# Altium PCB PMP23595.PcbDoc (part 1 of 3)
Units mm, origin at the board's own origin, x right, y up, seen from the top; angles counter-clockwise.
Board outline 121.92 x 78.74 mm, 6 copper layers (Layer 1, GND 1, Layer 3, Layer 4, GND 2, Layer 6), stack 2.208 mm thick; 236 components, 76 nets, 570 pads, 735 vias.
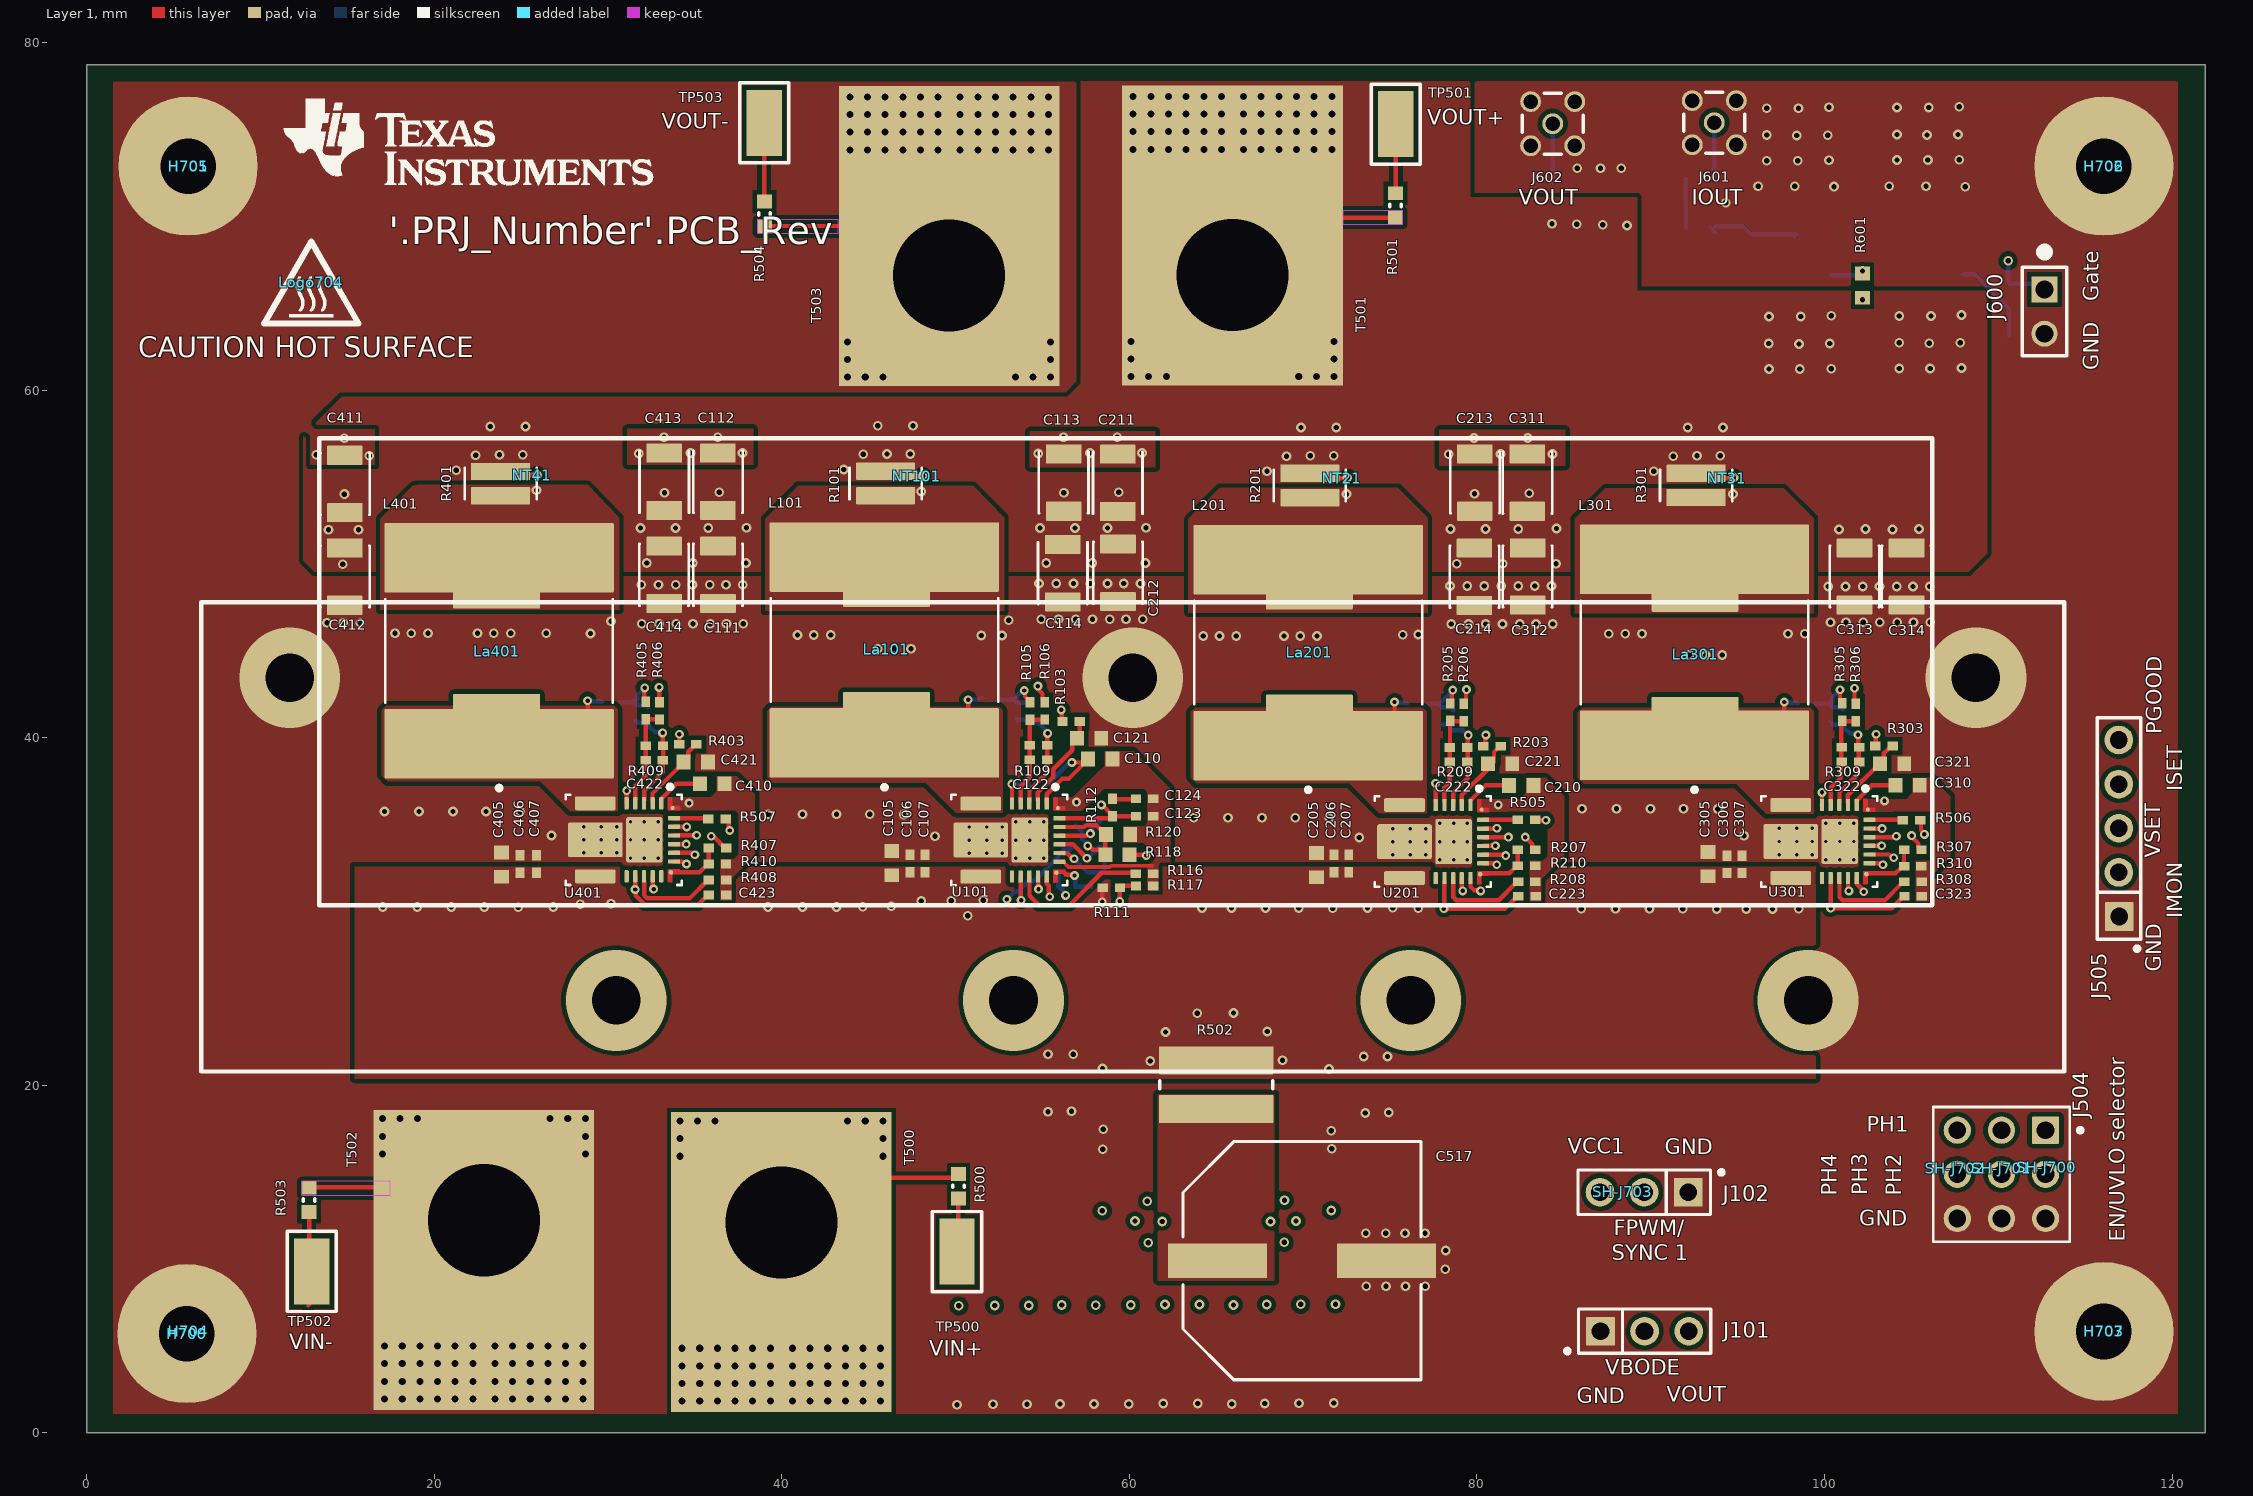
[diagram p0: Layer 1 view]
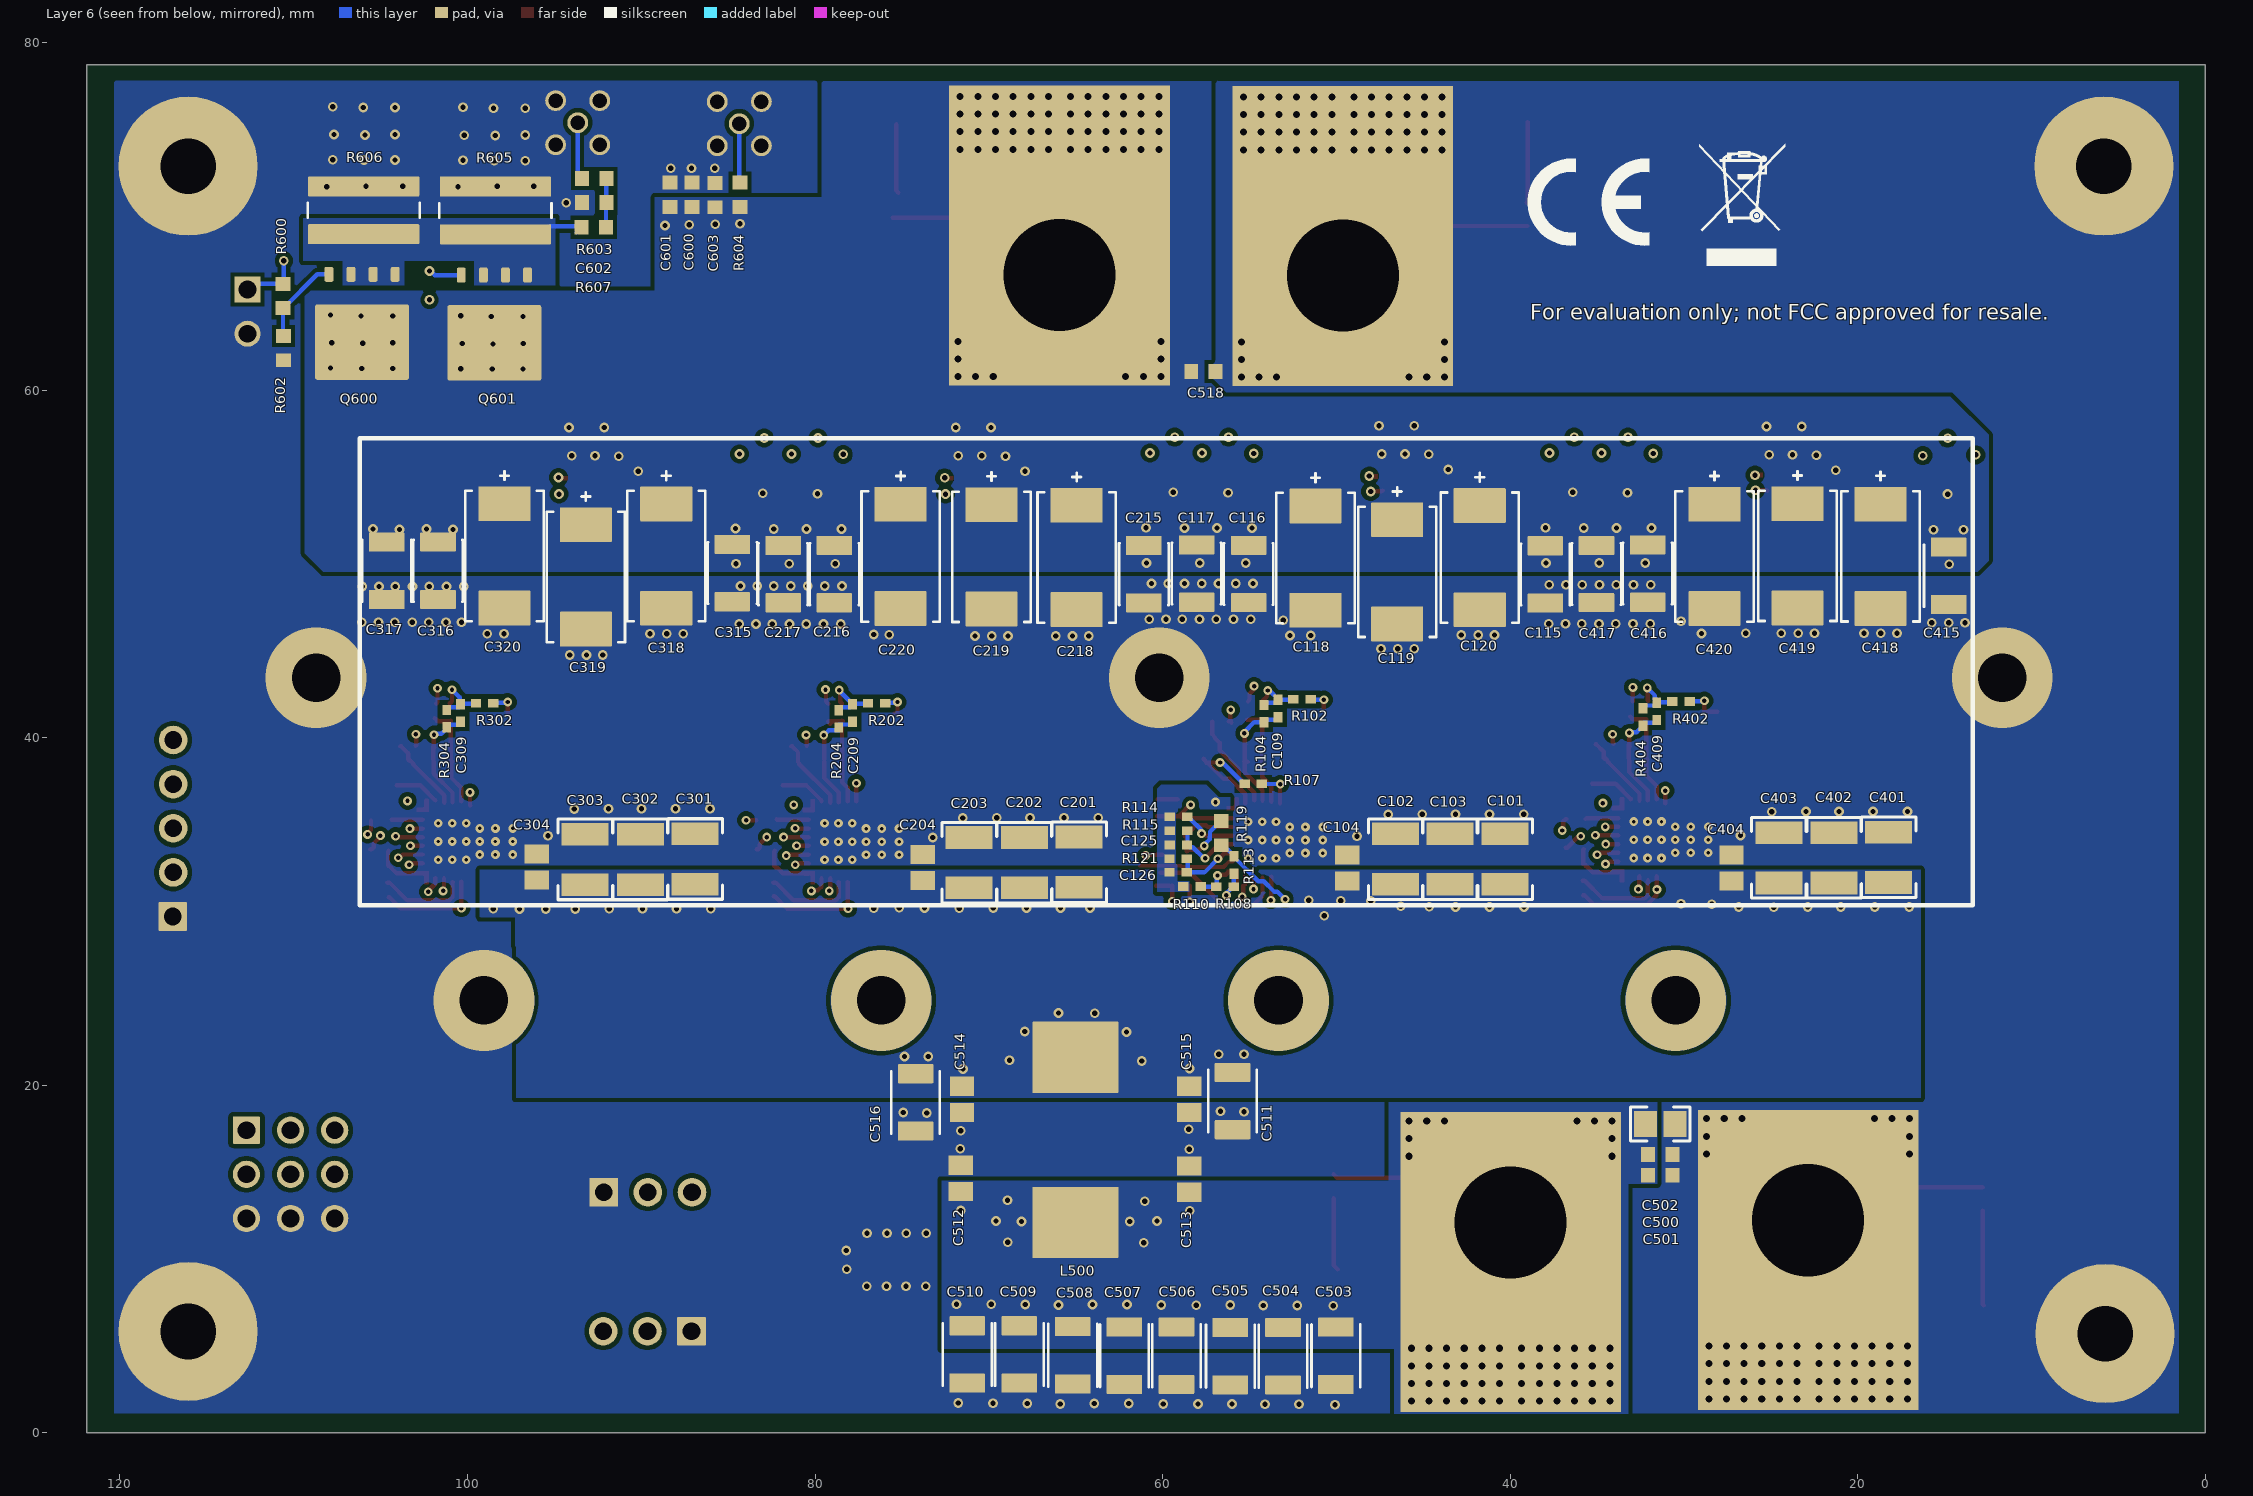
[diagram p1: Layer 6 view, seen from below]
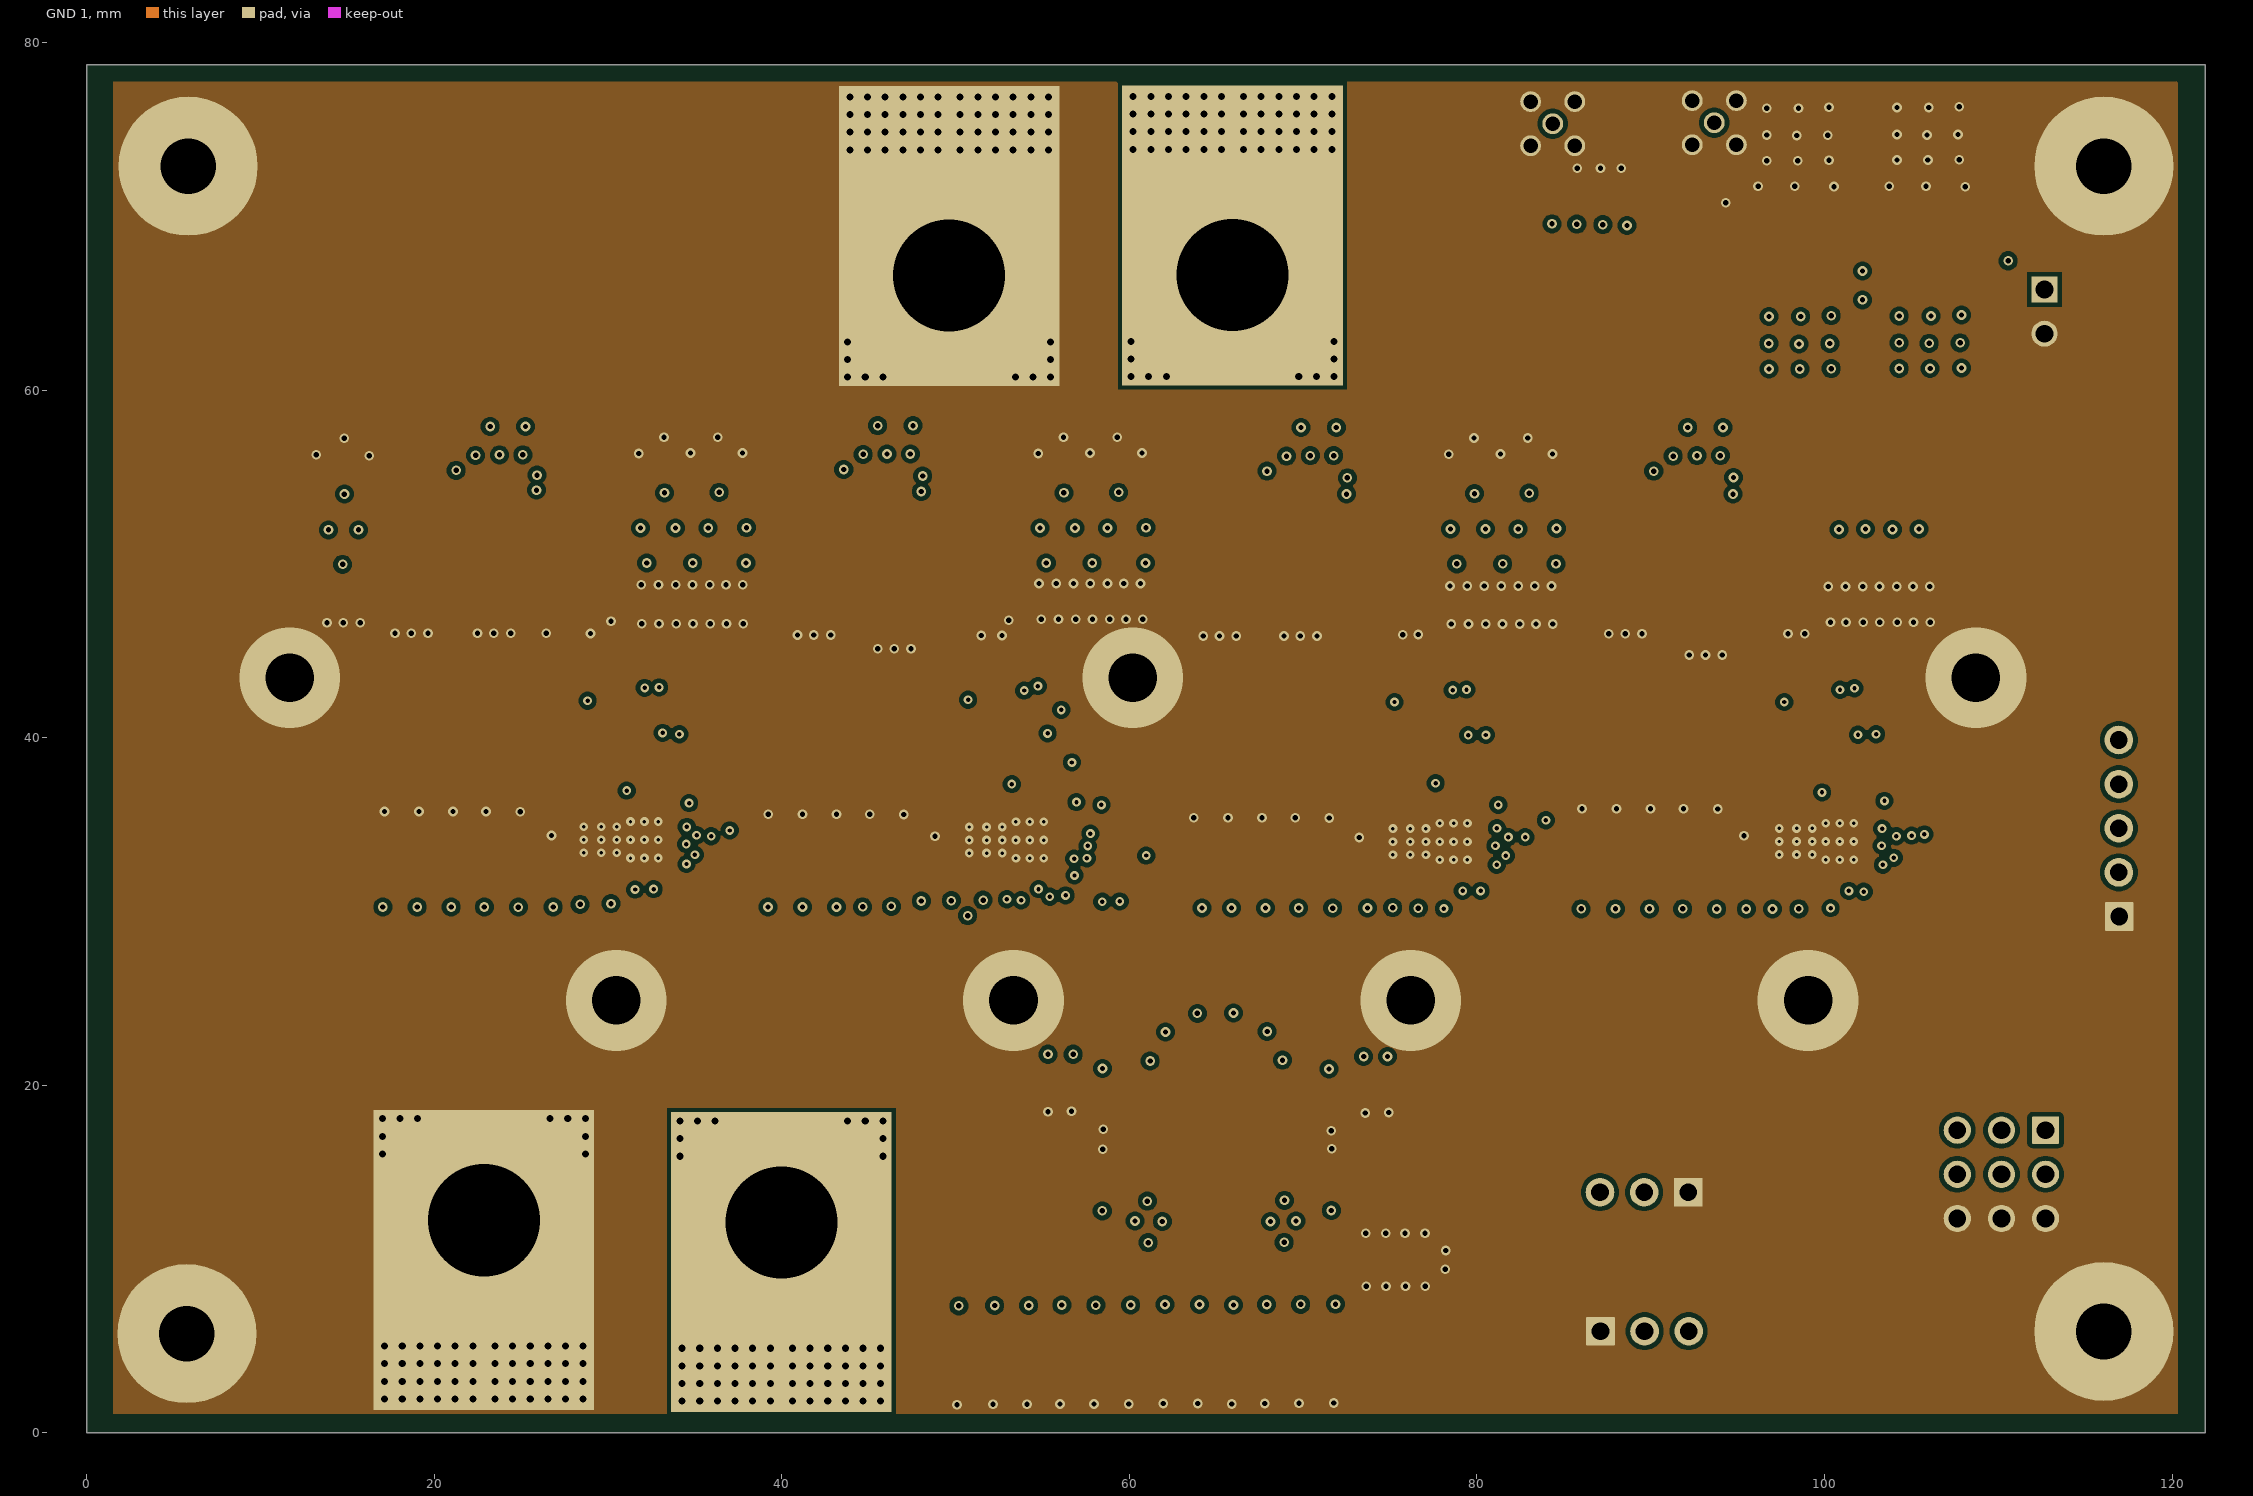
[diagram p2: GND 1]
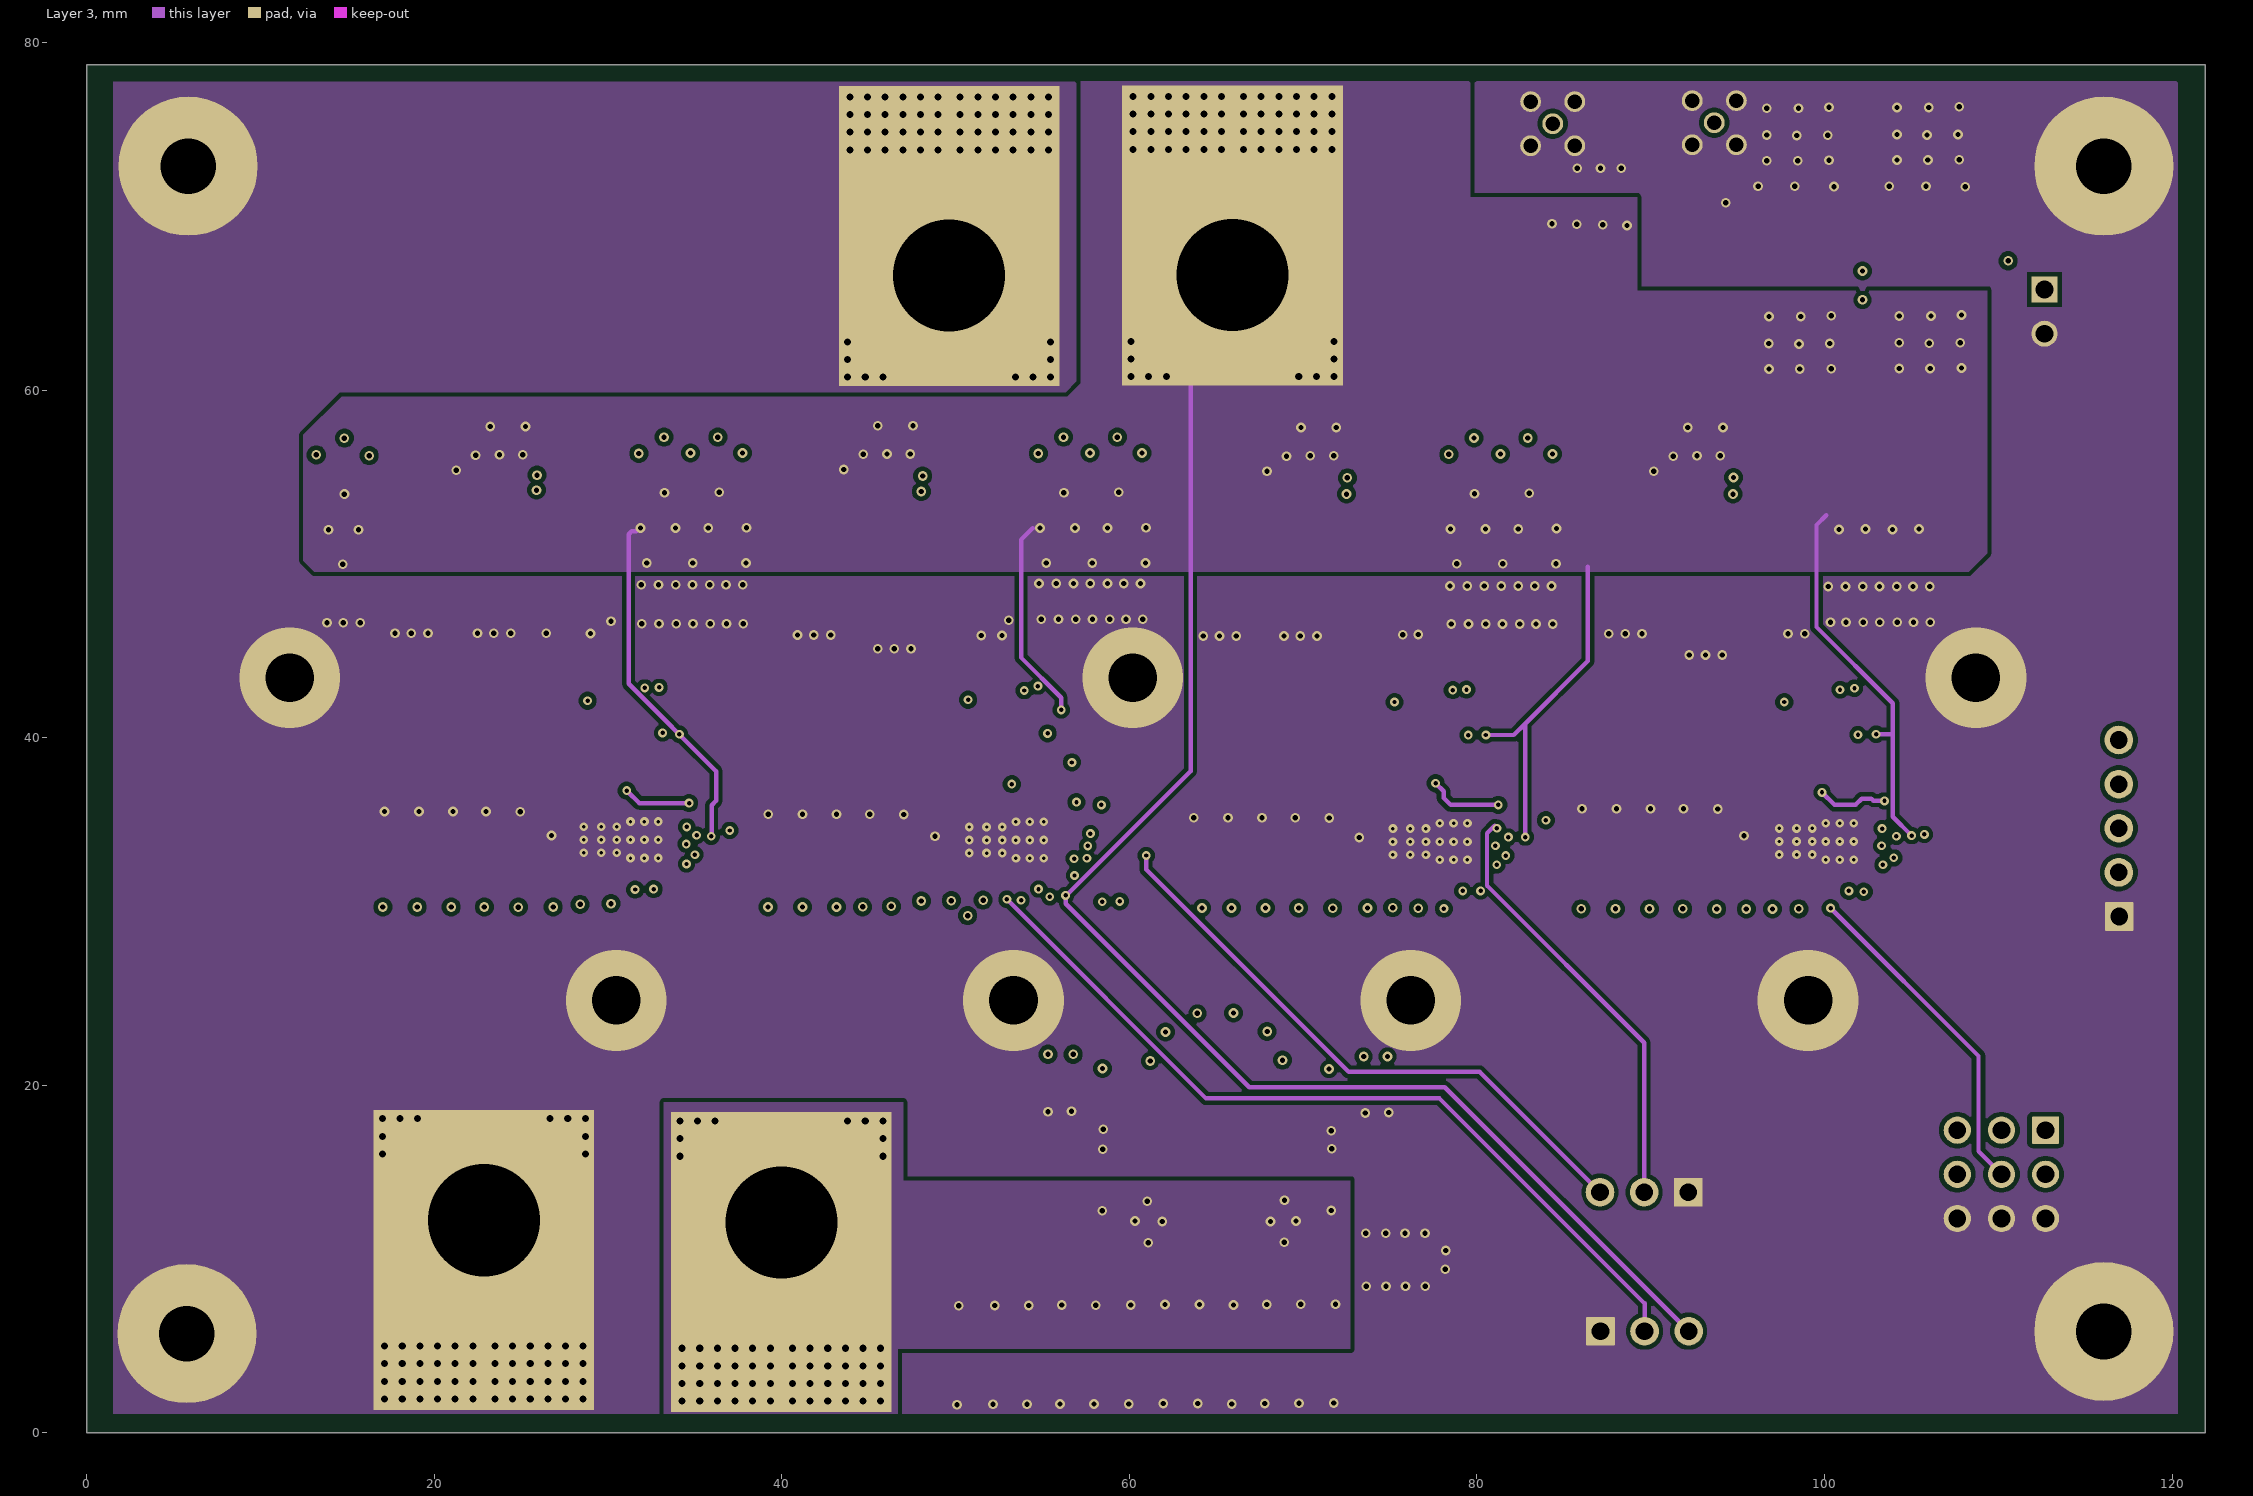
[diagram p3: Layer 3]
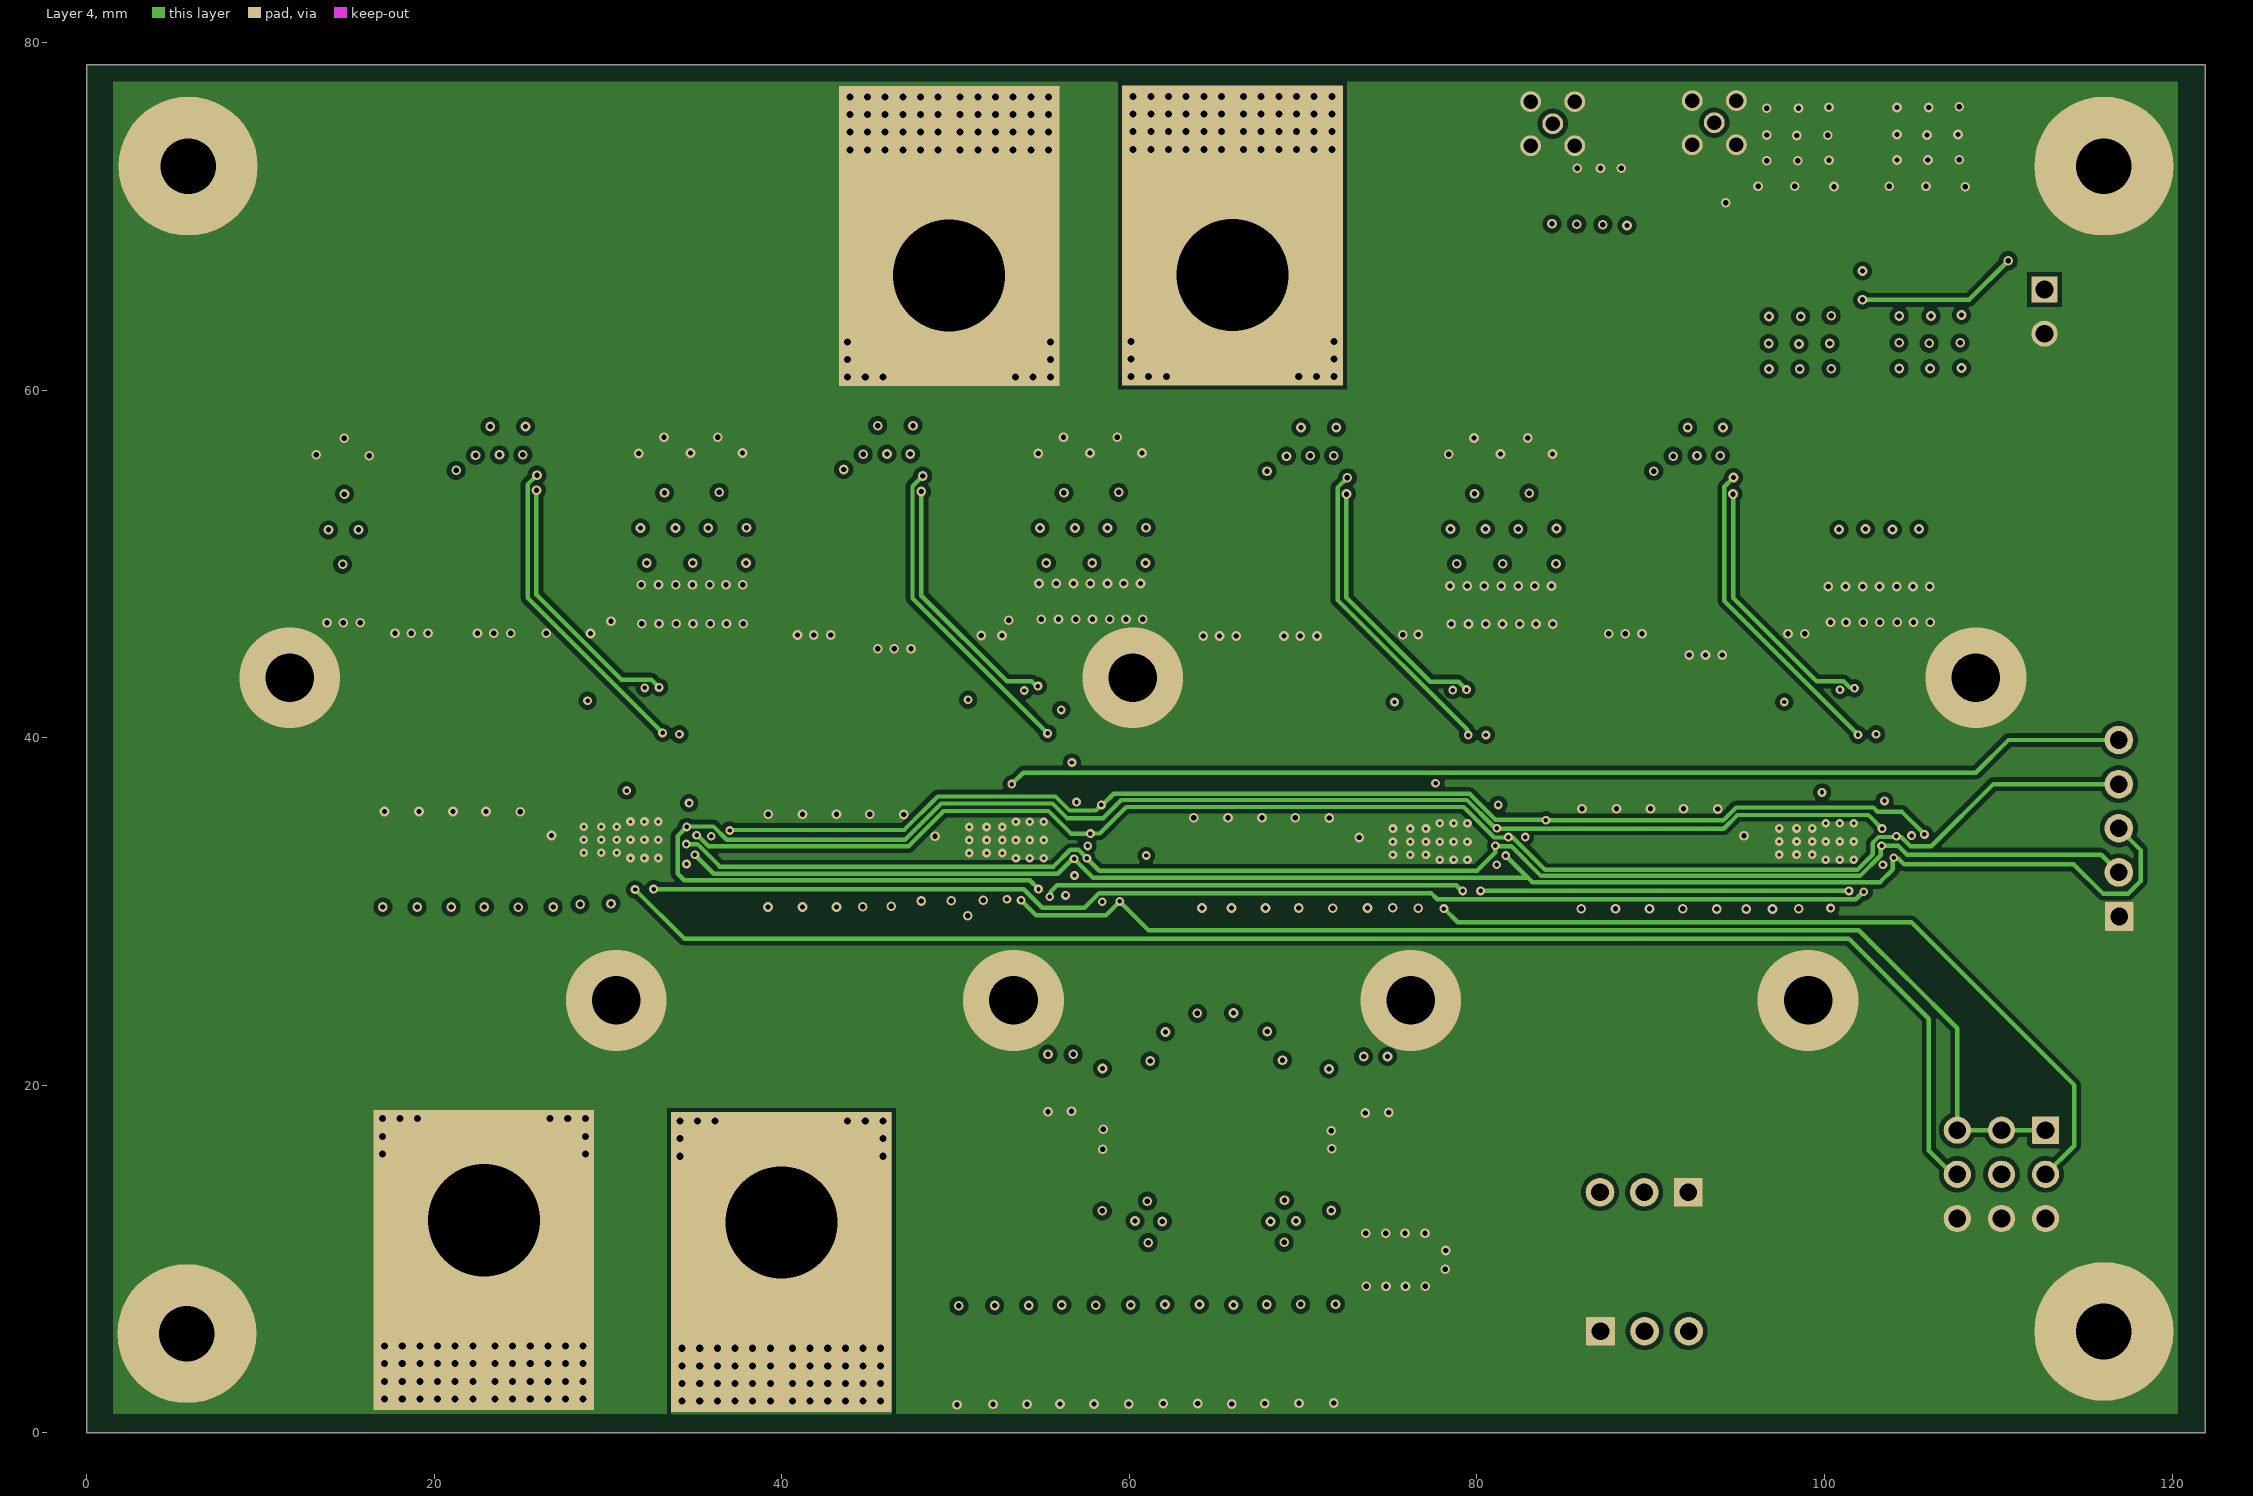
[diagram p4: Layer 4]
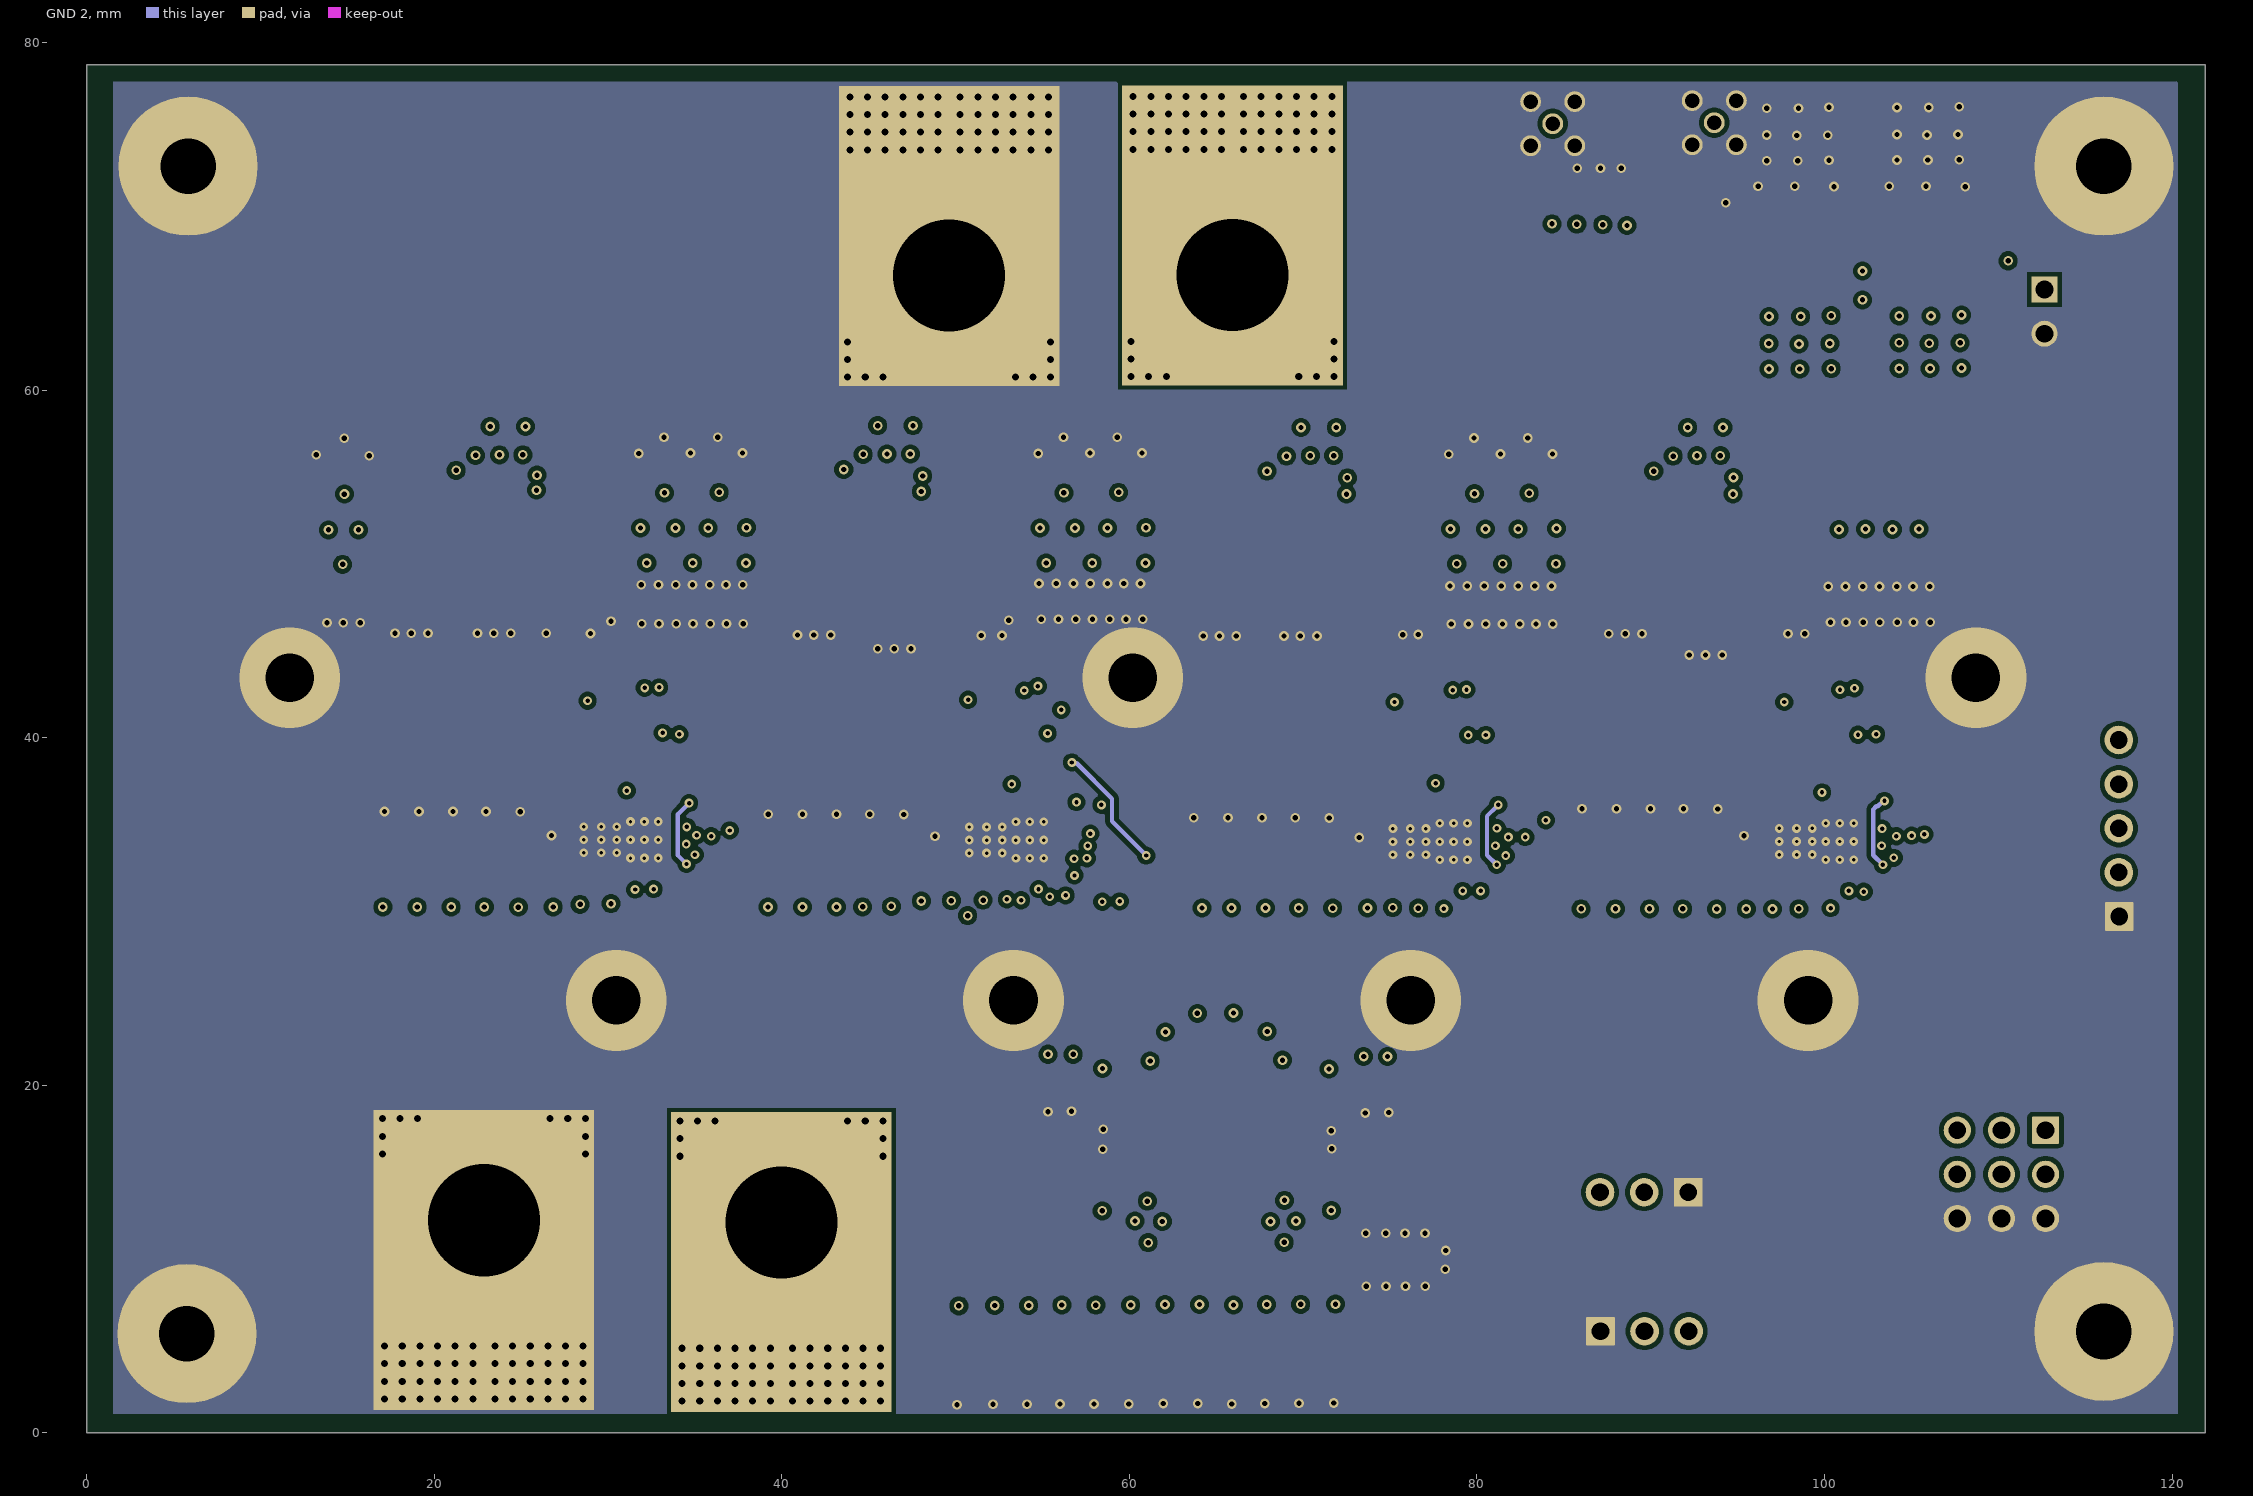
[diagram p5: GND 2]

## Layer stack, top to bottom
Top Solder: solder mask 0.0102, Solder Resist, Dk 3.5
Layer 1: signal copper 0.07
Dielectric 1: prepreg 0.0711, PP-006, Dk 4.1
GND 1: signal copper 0.07
Dielectric 3: prepreg 0.0711, PP-006, Dk 4.1
Layer 3: signal copper 0.07
Dielectric1: core 1.5037, FR-4 High Tg, Dk 4.8
Layer 4: signal copper 0.07
Dielectric 4: prepreg 0.0711, PP-006, Dk 4.1
GND 2: signal copper 0.07
Dielectric 2: prepreg 0.0711, PP-006, Dk 4.1
Layer 6: signal copper 0.07
Bottom Solder: solder mask 0.0102, Solder Resist, Dk 3.5

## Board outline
0,0 0,78.74 121.92,78.74 121.92,0

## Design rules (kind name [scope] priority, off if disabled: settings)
AcuteAngle [All] p1: minimum=4.50000000000000E+0001 checktracksonly=FALSE
AssemblyTestPointUsage [All] p1: valid=2
BoardOutlineClearance BoardOutlineClearance_MountingHoles [OnCopper and InComponentClass('Mounting Holes')] p1: gap=1 ignorepadtopadclearanceinfootprint=FALSE
BoardOutlineClearance BoardOutlineClearance_Poly [OnCopper and IsPoly] p2: gap=0.635 ignorepadtopadclearanceinfootprint=FALSE
BoardOutlineClearance [OnCopper and Not InComponentClass('Logo') and not InComponentClass('FiducialMark') and not InRegion(1000,500,4000,800) and not InPoly] p3: gap=1.016 ignorepadtopadclearanceinfootprint=FALSE
Clearance Clearance_Keepouts [((IsTrack Or IsArc) And Not InPoly) And IsFree and IsKeepOut vs ((IsTrack Or IsArc) And Not InPoly) And IsFree and IsKeepOut] p1: gap=0 ignorepadtopadclearanceinfootprint=FALSE
Clearance Clearance_Poly [InPolygon] p2: gap=0.254 ignorepadtopadclearanceinfootprint=TRUE
Clearance Clearance_FiducialMark [IsKeepOut and InComponentClass('FiducialMark') vs IsPad and InComponentClass('FiducialMark')] p3: gap=0 ignorepadtopadclearanceinfootprint=FALSE
Clearance [All] p4: gap=0.1 ignorepadtopadclearanceinfootprint=TRUE except(0.15: SMDPad-SMDPad; 0.2: Arc-Hole Track-Hole SMDPad-Hole THPad-Hole)
ComponentClearance ComponentClearance_MountingHoles_FiducialMarks [InComponentClass('Mounting Holes') vs InComponentClass('FiducialMark')] p1: gap=1.27 collisioncheckmode=3 verticalgap=0.254 showdistances=FALSE
ComponentClearance ComponentClearance_Shunt [InComponentClass('Header') vs InComponentClass('Shunt')] p2: gap=0 collisioncheckmode=3 verticalgap=0 showdistances=FALSE
ComponentClearance ComponentClearance_Logo [InComponentClass('Logo')] p3: gap=0.762 collisioncheckmode=3 verticalgap=0.254 showdistances=FALSE
ComponentClearance ComponentClearance_ScrewToNut [(HasFootprint('NY PMS 440 0025 PH')) vs (HasFootprint('Keystone_1902C'))] p4: gap=0.127 collisioncheckmode=3 verticalgap=0.254 showdistances=FALSE
ComponentClearance ComponentClearance_MountingHoles [InComponentClass('Mounting Holes')] p5: gap=2.54 collisioncheckmode=3 verticalgap=2540 showdistances=FALSE
ComponentClearance ComponentClearance_SmallPassives [HasFootprint('0201*') or HasFootprint('0402*') or HasFootprint('0508') or HasFootprint('0603*') or HasFootprint('0612') or HasFootprint('0805*') or HasFootprint('0815*') or HasFootprint('0830*') or HasFootprint('1206*') or HasFootprint('1210*') or HasFootprint('1808*') or HasFootprint('1812*') or HasFootprint('1825*') or HasFootprint('2010*') or HasFootprint('2220*') or HasFootprint('2225*') or HasFootprint('2512*') or HasFootprint('2728*') or HasFootprint('3518*') vs HasFootprint('0201*') or HasFootprint('0402*') or HasFootprint('0508') or HasFootprint('0603*') or HasFootprint('0612') or HasFootprint('0805*') or HasFootprint('0815*') or HasFootprint('0830*') or HasFootprint('1206*') or HasFootprint('1210*') or HasFootprint('1808*') or HasFootprint('1812*') or HasFootprint('1825*') or HasFootprint('2010*') or HasFootprint('2220*') or HasFootprint('2225*') or HasFootprint('2512*') or HasFootprint('2728*') or HasFootprint('3518*')] p6: gap=0.38 collisioncheckmode=3 verticalgap=0.254 showdistances=FALSE
ComponentClearance ComponentClearance_THtoSMT [IsThruComponent vs IsSMTComponent] p7: gap=0.762 collisioncheckmode=3 verticalgap=0.762 showdistances=FALSE
ComponentClearance ComponentClearance_THtoTH [IsThruComponent vs IsThruComponent] p8: gap=0.508 collisioncheckmode=3 verticalgap=0.762 showdistances=FALSE
ComponentClearance [All] p9: gap=0.508 collisioncheckmode=3 verticalgap=0.254 showdistances=FALSE
DiffPairsRouting [All] p1: maxlimit=2.54 minlimit=0.254 mostfreqgap=0.254 toplayer_minwidth=0.381 toplayer_maxwidth=0.381 toplayer_prefwidth=0.381 midlayer1_minwidth=0.381 midlayer1_maxwidth=0.381 midlayer1_prefwidth=0.381 midlayer2_minwidth=0.381 midlayer2_maxwidth=0.381 midlayer2_prefwidth=0.381 midlayer3_minwidth=0.381 midlayer3_maxwidth=0.381 midlayer3_prefwidth=0.381 midlayer4_minwidth=0.381 midlayer4_maxwidth=0.381 midlayer4_prefwidth=0.381 bottomlayer_minwidth=0.381 bottomlayer_maxwidth=0.381 bottomlayer_prefwidth=0.381 maxuncoupledlength=25.4
FabricationTestPointUsage TestPointUsage [All] p1: valid=2 allowmultiple=FALSE
FabricationTestpoint Testpoint [All] p1: side=3 testpointundercomponent=TRUE minsize=1.016 maxsize=2.54 preferedsize=1.524 minholesize=0 maxholesize=1.016 preferedholesize=0.813 testpointgrid=0.025 allowsidetop=TRUE allowsidebottom=TRUE usegrid=TRUE gridtolerance=0
FanoutControl Fanout_LCC [IsLCC] p1: bgadir=Out bgaviamode=Centered fanoutstyle=Auto fanoutdirection=Alternating viagrid=0.025 // Fanout_LCC (Default Rule)
FanoutControl Fanout_BGA [IsBGA] p2: bgadir=Out bgaviamode=Centered fanoutstyle=Auto fanoutdirection=Alternating viagrid=0.025 // Fanout_BGA (Default Rule)
FanoutControl Fanout_Default [All] p4: bgadir=Out bgaviamode=Centered fanoutstyle=Auto fanoutdirection=Alternating viagrid=0.025 // Fanout_Default (Default Rule)
FanoutControl Fanout_Small [(CompPinCount < 5)] p5: bgadir=Out bgaviamode=Centered fanoutstyle=Auto fanoutdirection=OutThenIn viagrid=0.025 // Fanout_Small (Default Rule)
HoleSize [All] p1: absolutevalues=TRUE maxlimit=7.62 minlimit=0.15 maxpercent=80.000 minpercent=20.000
HoleToHoleClearance [All] p1: gap=0.45 allowstackedmicrovias=TRUE
MinimumAnnularRing MinimumAnnularRing_ThermalPadVias [IsVia and InAnyComponent] p1: minimumring=0.075
MinimumAnnularRing [All] p2: minimumring=0.075
MinimumSolderMaskSliver MinimumSolderMaskSliver_Logo [InComponentClass('Logo') vs InComponentClass('Logo')] p1: minsoldermaskwidth=0.018
MinimumSolderMaskSliver [All] p2: minsoldermaskwidth=0.1
PlaneConnect [All] p1: planeconnectstyle=Relief reliefexpansion=0.254 reliefentries=4 reliefconductorwidth=0.254 reliefairgap=0.254
PolygonConnect [All] p1: connectstyle=Direct reliefconductorwidth=0.254 reliefentries=4 polygonreliefangle="90 Angle" airgapwidth=0.254
RoomDefinition 2 [InComponentClass('2')] p1: confinementstyle=ConfineIn formatcopy=TRUE lockcomponents=FALSE outline 57.301,51.868 57.301,57.484 77.85,57.496 81.916,57.496 83.847,52.13 84.314,38.343 84.338,31.794 84.338,29.978 81.422,29.978 64.728,30.082 61.578,30.107 57.316,46.689
RoomDefinition 1 [InComponentClass('1')] p2: confinementstyle=ConfineIn formatcopy=TRUE lockcomponents=FALSE outline 34.289,51.929 34.289,57.545 38.355,57.545 58.257,57.499 116.983,44.544 116.983,38.718 93.586,11.053 83.978,11.053 37.013,30.107 34.298,46.575
RoomDefinition 3 [InComponentClass('3')] p3: confinementstyle=ConfineIn formatcopy=TRUE lockcomponents=FALSE outline 80.873,51.878 80.873,57.494 84.939,57.494 100.709,55.925 106.656,52.318 106.656,46.902 106.656,46.476 106.563,29.978 103.647,29.978 86.953,30.089 83.803,30.114 80.887,46.476
RoomDefinition 4 [InComponentClass('4')] p4: confinementstyle=ConfineIn formatcopy=TRUE lockcomponents=FALSE outline 12.724,46.471 12.724,52.087 12.801,57.418 31.204,57.542 35.27,57.542 37.046,52.135 37.753,38.446 37.766,32.729 37.766,30.913 37.755,30.055 34.839,30.055 18.167,30.186 15.017,30.211
RoutingVias ThermalPadVias [IsVia and InAnyComponent] p1: holewidth=0.254 width=0.508 viastyle="Through Hole" minholewidth=0.15 minwidth=0.25 maxholewidth=5.08 maxwidth=7.62
RoutingVias [All] p2: holewidth=0.406 width=0.864 viastyle="Through Hole" minholewidth=0.254 minwidth=0.508 maxholewidth=5.08 maxwidth=7.62
SilkToBoardRegionClearance [Not ((IsComment or IsDesignator) And (Hide <> 'False')) and not InRegion(1000,500,4000,800)] p1:
SilkToSilkClearance SilkToSilkClearance_Pb-FreeLogo [(HasFootprint('Pb-Free_Overlay_Medium') OR HasFootprint('Pb-Free_Overlay_Small')) vs (HasFootprint('Pb-Free_Overlay_Medium') OR HasFootprint('Pb-Free_Overlay_Small'))] p1: silktosilkclearance=0
SilkToSilkClearance [All] p2: silktosilkclearance=0.1
SilkToSolderMaskClearance SilkToComponentPadClearance [(IsPad or IsFill or IsRegion) and InAnycomponent] p1: minsilkscreentomaskgap=0.15 clearancetoexposedcopper=TRUE
SilkToSolderMaskClearance "Silk to Solder Mask Opening" [All] p2: minsilkscreentomaskgap=0.1 clearancetoexposedcopper=FALSE
SolderMaskExpansion [All] p1: expansion=0.05 istentingtop=FALSE
UnRoutedNet [All] p1: checkbadconnections=TRUE
Width [All] p1: maxlimit=2.54 minlimit=0.152 preferedwidth=0.254 checkconnectedcopper=TRUE
13 further rules are at their usual default settings.

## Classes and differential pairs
component class "Mounting Holes": H700 H701 H702 H703
component class Logo: Logo701
component class Header: J101 J102 J505 J600
component class AssemblyNote: ZZ700 ZZ701 ZZ702 ZZ703
component class U_Hardware: !PCB700 H700 H701 H702 H703 H704 H705 H706 H707 Logo700 Logo701 Logo702 Logo703 Logo704 SH-J700 SH-J701 SH-J702 SH-J703 ZZ700 ZZ701 ZZ702 ZZ703
channel class ModularPhases: 2 3 4
net class HV: VBAT+ VFILTER
component class U_DynamicLoad: C600 C601 C602 C603 J600 J601 J602 Q600 Q601 R600 R601 R602 R603 R604 R605 R606 R607
component class TopSheet: C500 C501 C502 C503 C504 C505 C506 C507 C508 C509 C510 C511 C512 C513 C514 C515 C516 C517 C518 J504 J505 L500 R500 R501 R502 R503 R504 R505 R506 R507 T500 T501 T502 T503 TP500 TP501 TP502 TP503
component class 4: C401 C402 C403 C404 C405 C406 C407 C409 C410 C411 C412 C413 C414 C415 C416 C417 C418 C419 C420 C421 C422 C423 L401 La401 NT41 R401 R402 R403 R404 R405 R406 R407 R408 R409 R410 U401
component class 3: C301 C302 C303 C304 C305 C306 C307 C309 C310 C311 C312 C313 C314 C315 C316 C317 C318 C319 C320 C321 C322 C323 L301 La301 NT31 R301 R302 R303 R304 R305 R306 R307 R308 R309 R310 U301
component class 2: C201 C202 C203 C204 C205 C206 C207 C209 C210 C211 C212 C213 C214 C215 C216 C217 C218 C219 C220 C221 C222 C223 L201 La201 NT21 R201 R202 R203 R204 R205 R206 R207 R208 R209 R210 U201
component class 1: C101 C102 C103 C104 C105 C106 C107 C109 C110 C111 C112 C113 C114 C115 C116 C117 C118 C119 C120 C121 C122 C123 C124 C125 C126 Ca J101 J102 L101 La101 NT101 R101 R102 R103 R104 R105 R106 R107 R108 R109 R110 R111 R112 R113 R114 R115 R116 R117 R118 R119 R120 R121 U101

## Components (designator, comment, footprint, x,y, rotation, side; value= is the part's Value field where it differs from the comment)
C101 "GCM32DC72A475KE02L" 1210_220 40.296,33.02 r90 bottom value=4.7uF
C102 "GCM32DC72A475KE02L" 1210_220 46.595,33.02 r90 bottom value=4.7uF
C103 "GCM32DC72A475KE02L" 1210_220 43.471,33.02 r90 bottom value=4.7uF
C104 "CGA4J3X7S2A105K125AB" 0805L 49.378,32.512 r90 bottom value=1uF
C105 "HMK107B7104MAHT" 0603L 46.33,32.791 r90 top value=0.1uF
C106 "CGA2B3X7S2A103K050BB" 0402L 47.382,32.766 r90 top value=0.01uF
C107 "CGA2B3X7S2A102K050BB" 0402L 48.246,32.766 r90 top value=1000pF
C109 "CGA2B3X7R1E104K050BB" 0402L 53.365,41.681 r270 bottom value=0.1uF
C110 "GRT188R61C475KE13D" 0603L 58.333,38.79 r0 top value=4.7uF
C111 "GCM32EC71E226KE36L" FP-GCM32EC71E226KE36L_1210-MFG 36.331,49.383 r270 top value=22µF
C112 "GCM32EC71E226KE36L" FP-GCM32EC71E226KE36L_1210-MFG 36.322,54.737 r90 top value=22µF
C113 "GCM32EC71E226KE36L" FP-GCM32EC71E226KE36L_1210-MFG 56.171,49.475 r270 top value=22µF
C114 "GCM32EC71E226KE36L" FP-GCM32EC71E226KE36L_1210-MFG 56.224,54.691 r90 top value=22µF
C115 "GCM32EC71E226KE36L" FP-GCM32EC71E226KE36L_1210-MFG 37.984,49.403 r270 bottom value=22µF
C116 "GCM32EC71E226KE36L" FP-GCM32EC71E226KE36L_1210-MFG 55.053,49.428 r270 bottom value=22µF
C117 "GCM32EC71E226KE36L" FP-GCM32EC71E226KE36L_1210-MFG 58.05,49.454 r270 bottom value=22µF
C118 "TCQE157M016R0025E" FP-TCQE157M016R0025E_2917-MFG 51.206,50.343 r90 bottom value=150µF
C119 "TCQE157M016R0025E" FP-TCQE157M016R0025E_2917-MFG 46.507,49.553 r90 bottom value=150µF
C120 "TCQE157M016R0025E" FP-TCQE157M016R0025E_2917-MFG 41.758,50.368 r90 bottom value=150µF
C121 "CGA3E1X7R1V105K080AE" 0603L 57.683,39.98 r0 top value=1uF
C122 "CGA2B2C0G1H470J050BA" 0402L 54.774,38.735 r0 top value=47pF
C123 "CGA2B2C0G1H151J050BA" 0402L 60.884,35.484 r0 top value=150pF
C124 "CGA2B3X7S2A682K050BB" 0402L 60.884,36.5 r0 top value=6800pF
C125 "CGA2B3X7R1E104K050BB" 0402L 59.102,33.835 r0 bottom value=0.1uF
C126 "CGA2B3X7R1E104K050BB" 0402L 59.106,32.258 r0 bottom value=0.1uF
C201 "GCM32DC72A475KE02L" 1210_220 64.81,32.843 r90 bottom value=4.7uF (schematic designator C01)
C202 "GCM32DC72A475KE02L" 1210_220 67.959,32.817 r90 bottom value=4.7uF (schematic designator C02)
C203 "GCM32DC72A475KE02L" 1210_220 71.134,32.817 r90 bottom value=4.7uF (schematic designator C03)
C204 "CGA4J3X7S2A105K125AB" 0805L 73.801,32.538 r90 bottom value=1uF (schematic designator C04)
C205 "HMK107B7104MAHT" 0603L 70.767,32.678 r90 top value=0.1uF (schematic designator C05)
C206 "CGA2B3X7S2A103K050BB" 0402L 71.783,32.767 r90 top value=0.01uF (schematic designator C06)
C207 "CGA2B3X7S2A102K050BB" 0402L 72.622,32.767 r90 top value=1000pF (schematic designator C07)
C209 "CGA2B3X7R1E104K050BB" 0402L 77.854,41.422 r270 bottom value=0.1uF (schematic designator C09)
C210 "GRT188R61C475KE13D" 0603L 82.556,37.26 r0 top value=4.7uF (schematic designator C10)
C211 "GCM32EC71E226KE36L" FP-GCM32EC71E226KE36L_1210-MFG 59.334,54.676 r90 top value=22µF (schematic designator C11)
C212 "GCM32EC71E226KE36L" FP-GCM32EC71E226KE36L_1210-MFG 59.349,49.497 r270 top value=22µF (schematic designator C12)
C213 "GCM32EC71E226KE36L" FP-GCM32EC71E226KE36L_1210-MFG 79.883,54.688 r90 top value=22µF (schematic designator C13)
C214 "GCM32EC71E226KE36L" FP-GCM32EC71E226KE36L_1210-MFG 79.858,49.274 r270 top value=22µF (schematic designator C14)
C215 "GCM32EC71E226KE36L" FP-GCM32EC71E226KE36L_1210-MFG 61.087,49.417 r270 bottom value=22µF (schematic designator C15)
C216 "GCM32EC71E226KE36L" FP-GCM32EC71E226KE36L_1210-MFG 78.892,49.422 r270 bottom value=22µF (schematic designator C16)
C217 "GCM32EC71E226KE36L" FP-GCM32EC71E226KE36L_1210-MFG 81.839,49.422 r270 bottom value=22µF (schematic designator C17)
C218 "TCQE157M016R0025E" FP-TCQE157M016R0025E_2917-MFG 64.953,50.382 r90 bottom value=150µF (schematic designator C18)
C219 "TCQE157M016R0025E" FP-TCQE157M016R0025E_2917-MFG 69.85,50.419 r90 bottom value=150µF (schematic designator C19)
C220 "TCQE157M016R0025E" FP-TCQE157M016R0025E_2917-MFG 75.082,50.442 r90 bottom value=150µF (schematic designator C20)
C221 "CGA3E1X7R1V105K080AE" 0603L 81.334,38.507 r0 top value=1uF (schematic designator C21)
C222 "CGA2B2C0G1H470J050BA" 0402L 78.946,38.609 r0 top value=47pF (schematic designator C22)
C223 "CGA2B2NP01H470J050BA" 0402L 82.88,30.886 r0 top value=47pF (schematic designator C23)
C301 "GCM32DC72A475KE02L" 1210_220 86.908,33.028 r90 bottom value=4.7uF (schematic designator C01)
C302 "GCM32DC72A475KE02L" 1210_220 90.057,33.002 r90 bottom value=4.7uF (schematic designator C02)
C303 "GCM32DC72A475KE02L" 1210_220 93.232,33.002 r90 bottom value=4.7uF (schematic designator C03)
C304 "CGA4J3X7S2A105K125AB" 0805L 96.026,32.57 r90 bottom value=1uF (schematic designator C04)
C305 "HMK107B7104MAHT" 0603L 93.297,32.735 r90 top value=0.1uF (schematic designator C05)
C306 "CGA2B3X7S2A103K050BB" 0402L 94.389,32.723 r90 top value=0.01uF (schematic designator C06)
C307 "CGA2B3X7S2A102K050BB" 0402L 95.253,32.723 r90 top value=1000pF (schematic designator C07)
C309 "CGA2B3X7R1E104K050BB" 0402L 100.409,41.429 r270 bottom value=0.1uF (schematic designator C09)
C310 "GRT188R61C475KE13D" 0603L 104.781,37.267 r0 top value=4.7uF (schematic designator C10)
C311 "GCM32EC71E226KE36L" FP-GCM32EC71E226KE36L_1210-MFG 82.906,54.686 r90 top value=22µF (schematic designator C11)
C312 "GCM32EC71E226KE36L" FP-GCM32EC71E226KE36L_1210-MFG 82.92,49.284 r270 top value=22µF (schematic designator C12)
C313 "GCM32EC71E226KE36L" FP-GCM32EC71E226KE36L_1210-MFG 101.727,49.284 r270 top value=22µF (schematic designator C13)
C314 "GCM32EC71E226KE36L" FP-GCM32EC71E226KE36L_1210-MFG 104.724,49.284 r270 top value=22µF (schematic designator C14)
C315 "GCM32EC71E226KE36L" FP-GCM32EC71E226KE36L_1210-MFG 84.76,49.483 r270 bottom value=22µF (schematic designator C15)
C316 "GCM32EC71E226KE36L" FP-GCM32EC71E226KE36L_1210-MFG 101.702,49.61 r270 bottom value=22µF (schematic designator C16)
C317 "GCM32EC71E226KE36L" FP-GCM32EC71E226KE36L_1210-MFG 104.648,49.61 r270 bottom value=22µF (schematic designator C17)
C318 "TCQE157M016R0025E" FP-TCQE157M016R0025E_2917-MFG 88.565,50.459 r90 bottom value=150µF (schematic designator C18)
C319 "TCQE157M016R0025E" FP-TCQE157M016R0025E_2917-MFG 93.193,49.26 r90 bottom value=150µF (schematic designator C19)
C320 "TCQE157M016R0025E" FP-TCQE157M016R0025E_2917-MFG 97.876,50.467 r90 bottom value=150µF (schematic designator C20)
C321 "CGA3E1X7R1V105K080AE" 0603L 103.889,38.514 r0 top value=1uF (schematic designator C21)
C322 "CGA2B2C0G1H470J050BA" 0402L 101.501,38.616 r0 top value=47pF (schematic designator C22)
C323 "CGA2B2NP01H470J050BA" 0402L 105.105,30.886 r0 top value=47pF (schematic designator C23)
C401 "GCM32DC72A475KE02L" 1210_220 18.223,33.124 r90 bottom value=4.7uF (schematic designator C01)
C402 "GCM32DC72A475KE02L" 1210_220 21.373,33.099 r90 bottom value=4.7uF (schematic designator C02)
C403 "GCM32DC72A475KE02L" 1210_220 24.548,33.099 r90 bottom value=4.7uF (schematic designator C03)
C404 "CGA4J3X7S2A105K125AB" 0805L 27.265,32.515 r90 bottom value=1uF (schematic designator C04)
C405 "HMK107B7104MAHT" 0603L 23.876,32.705 r90 top value=0.1uF (schematic designator C05)
C406 "CGA2B3X7S2A103K050BB" 0402L 24.943,32.743 r90 top value=0.01uF (schematic designator C06)
C407 "CGA2B3X7S2A102K050BB" 0402L 25.883,32.743 r90 top value=1000pF (schematic designator C07)
C409 "CGA2B3X7R1E104K050BB" 0402L 31.572,41.526 r270 bottom value=0.1uF (schematic designator C09)
C410 "GRT188R61C475KE13D" 0603L 35.995,37.363 r0 top value=4.7uF (schematic designator C10)
C411 "GCM32EC71E226KE36L" FP-GCM32EC71E226KE36L_1210-MFG 14.859,54.61 r90 top value=22µF (schematic designator C11)
C412 "GCM32EC71E226KE36L" FP-GCM32EC71E226KE36L_1210-MFG 14.859,49.279 r270 top value=22µF (schematic designator C12)
C413 "GCM32EC71E226KE36L" FP-GCM32EC71E226KE36L_1210-MFG 33.237,54.734 r90 top value=22µF (schematic designator C13)
C414 "GCM32EC71E226KE36L" FP-GCM32EC71E226KE36L_1210-MFG 33.234,49.38 r270 top value=22µF (schematic designator C14)
C415 "GCM32EC71E226KE36L" FP-GCM32EC71E226KE36L_1210-MFG 14.769,49.326 r270 bottom value=22µF (schematic designator C15)
C416 "GCM32EC71E226KE36L" FP-GCM32EC71E226KE36L_1210-MFG 32.091,49.453 r270 bottom value=22µF (schematic designator C16)
C417 "GCM32EC71E226KE36L" FP-GCM32EC71E226KE36L_1210-MFG 35.038,49.427 r270 bottom value=22µF (schematic designator C17)
C418 "TCQE157M016R0025E" FP-TCQE157M016R0025E_2917-MFG 18.694,50.447 r90 bottom value=150µF (schematic designator C18)
C419 "TCQE157M016R0025E" FP-TCQE157M016R0025E_2917-MFG 23.47,50.473 r90 bottom value=150µF (schematic designator C19)
C420 "TCQE157M016R0025E" FP-TCQE157M016R0025E_2917-MFG 28.245,50.442 r90 bottom value=150µF (schematic designator C20)
C421 "CGA3E1X7R1V105K080AE" 0603L 35.052,38.611 r0 top value=1uF (schematic designator C21)
C422 "CGA2B2C0G1H470J050BA" 0402L 32.664,38.712 r0 top value=47pF (schematic designator C22)
C423 "CGA2B2NP01H470J050BA" 0402L 36.297,30.963 r0 top value=47pF (schematic designator C23)
C500 "GRM188R72A103KA01D" 0603L 31.369,16.029 r0 bottom value=0.01uF
C501 "CGA3E2X7R2A102K080AA" 0603L 31.369,14.834 r180 bottom value=1000pF
C502 "C0805C104K1RACTU" 0805 31.369,17.78 r180 bottom value=0.1uF
C503 "GCJ32DC72A475KE01L" FP-GCJ32DC72A475KE01L_1210-MFG 50.038,4.445 r90 bottom value=4.7µF
C504 "GCJ32DC72A475KE01L" FP-GCJ32DC72A475KE01L_1210-MFG 53.078,4.419 r90 bottom value=4.7µF
C505 "GCJ32DC72A475KE01L" FP-GCJ32DC72A475KE01L_1210-MFG 56.109,4.42 r90 bottom value=4.7µF
C506 "GCJ32DC72A475KE01L" FP-GCJ32DC72A475KE01L_1210-MFG 59.207,4.445 r90 bottom value=4.7µF
C507 "GCJ32DC72A475KE01L" FP-GCJ32DC72A475KE01L_1210-MFG 62.205,4.445 r90 bottom value=4.7µF
C508 "GCJ32DC72A475KE01L" FP-GCJ32DC72A475KE01L_1210-MFG 65.176,4.47 r90 bottom value=4.7µF
C509 "GCJ32DC72A475KE01L" FP-GCJ32DC72A475KE01L_1210-MFG 68.25,4.521 r90 bottom value=4.7µF
C510 "GCJ32DC72A475KE01L" FP-GCJ32DC72A475KE01L_1210-MFG 71.247,4.521 r90 bottom value=4.7µF
C511 "GRM21BR72A474KA73L" 0805L 58.471,14.605 r90 bottom value=0.47uF
C512 "GRM21BR72A474KA73L" 0805L 71.628,14.656 r90 bottom value=0.47uF
C513 "GRM21BR72A474KA73L" 0805L 58.471,19.202 r270 bottom value=0.47uF
C514 "GRM21BR72A474KA73L" 0805L 71.552,19.202 r270 bottom value=0.47uF
C515 "GCJ32DC72A475KE01L" FP-GCJ32DC72A475KE01L_1210-MFG 55.982,19.101 r90 bottom value=4.7µF
C516 "GCJ32DC72A475KE01L" FP-GCJ32DC72A475KE01L_1210-MFG 74.219,19.025 r90 bottom value=4.7µF
C517 "EEV-FK1K101Q" SM_RADIAL_H13 69.937,9.912 r0 top value=100uF
C518 "06035C104KAZ2A" 0603L 57.658,61.087 r180 bottom value=0.1uF
C600 "CGA3E2X7R2A102K080AA" 0603L 87.084,71.247 r90 bottom value=1000pF
C601 "GRM188R72A103KA01D" 0603L 88.354,71.247 r270 bottom value=0.01uF
C602 "CGA3E2X7R1E104K080AA" 0603L 92.713,70.811 r180 bottom value=0.1uF
C603 "CGA3E2X7R1E104K080AA" 0603L 85.763,71.234 r270 bottom value=0.1uF
H700 "NY PMS 440 0025 PH" "NY PMS 440 0025 PH"#1 5.842,5.842 r0 top
H701 "NY PMS 440 0025 PH" "NY PMS 440 0025 PH"#2 5.842,72.898 r0 top
H702 "NY PMS 440 0025 PH" "NY PMS 440 0025 PH"#2 116.078,72.898 r0 top
H703 "NY PMS 440 0025 PH" "NY PMS 440 0025 PH"#2 116.078,5.842 r0 top
H704 "1902E" Keystone_1902E 5.842,5.842 r0 top
H705 "1902E" Keystone_1902E 5.842,72.898 r0 top
H706 "1902E" Keystone_1902E 116.078,72.898 r0 top
H707 "1902E" Keystone_1902E 116.078,5.842 r0 top
J101 "HTSW-103-07-G-S" Samtec_HTSW-103-07-G-S 89.649,5.857 r0 top
J102 "HTSW-103-07-G-S" Samtec_HTSW-103-07-G-S 89.624,13.853 r180 top
J504 "TSW-103-07-G-T" FP-TSW-103-07-G-T_HDR9-MFG 110.185,14.884 r180 top
J505 "TSW-105-07-G-S" TSW-105-07-X-S 116.939,34.798 r90 top
J600 "5-146261-1" CONN_5-146261-1 112.661,64.526 r270 top
J601 "MMCX-J-P-H-ST-TH1" Samtec_MMCX-J-P-H-ST-TH1 93.659,75.398 r0 top
J602 "MMCX-J-P-H-ST-TH1" Samtec_MMCX-J-P-H-ST-TH1 84.362,75.339 r0 top
L101 "VCUD128T-4R7MS8" FP-VCUD128T-4R7MS8_SMT_IND_13MM3_12MM8-MFG 45.909,45.055 r90 top value=4.7uH
L201 "VCUD128T-4R7MS8" FP-VCUD128T-4R7MS8_SMT_IND_13MM3_12MM8-MFG 70.296,44.908 r90 top value=4.7uH (schematic designator L01)
L301 "VCUD128T-4R7MS8" FP-VCUD128T-4R7MS8_SMT_IND_13MM3_12MM8-MFG 92.521,44.915 r90 top value=4.7uH (schematic designator L01)
L401 "VCUD128T-4R7MS8" FP-VCUD128T-4R7MS8_SMT_IND_13MM3_12MM8-MFG 23.735,45.012 r90 top value=4.7uH (schematic designator L01)
L500 "VCHA105D-1R0MS6" VCHA105D 65.024,16.866 r90 bottom value=1uH
La101 "VCHA105D-4R7MS6" FP-VCHA105D-4R7MS6_SMT_10MM85_10MM0-MFG 46.025,45.085 r90 top value=4.7uH
La201 "VCHA105D-4R7MS6" FP-VCHA105D-4R7MS6_SMT_10MM85_10MM0-MFG 70.358,44.933 r90 top value=4.7uH (schematic designator La01)
La301 "VCHA105D-4R7MS6" FP-VCHA105D-4R7MS6_SMT_10MM85_10MM0-MFG 92.558,44.806 r90 top value=4.7uH (schematic designator La01)
La401 "VCHA105D-4R7MS6" FP-VCHA105D-4R7MS6_SMT_10MM85_10MM0-MFG 23.597,44.983 r90 top value=4.7uH (schematic designator La01)
Logo700 "CE Mark" CE_Mark_5mm 18.523,107.02 r180 bottom
Logo701 "Texas Instruments" TI_Stacked_Overlay_Small 38.938,110.49 r0 top
Logo702 "FCC disclaimer" FCC_disclaimer 1125.198,171.983 r90 bottom
Logo703 "WEEE logo" WEEE_Minimum 9.729,107.728 r180 bottom
Logo704 "CAUTION HOT SURFACE" IEC_HotSurface_Small 12.929,66.204 r0 top
NT21 "Net-Tie" Net-Tie_10mil 72.212,54.94 r180 top net-tie (schematic designator NT1)
NT31 "Net-Tie" Net-Tie_10mil 94.386,54.94 r180 top net-tie (schematic designator NT1)
NT41 "Net-Tie" Net-Tie_10mil 25.629,55.118 r180 top net-tie (schematic designator NT1)
NT101 "Net-Tie" Net-Tie_10mil 47.777,55.042 r180 top net-tie
Q600 "CSD17570Q5B" DNK0008A 106.07,63.853 r270 bottom value=30V
Q601 "CSD17570Q5B" DNK0008A 98.456,63.81 r270 bottom value=30V
R101 "KRL3216E-C-R001-J-T5" FP-KRL3216E-C-R001-J-T5_0612-MFG 45.974,54.635 r90 top value=1m
R102 "ERJPA2F1002X" 0402L 51.98,42.215 r0 bottom value=10.0k
R103 "RK73Z1ETTP" 0402L 56.653,40.94 r180 top value=0
R104 "RK73H1ETTP1002F" 0402L 54.174,41.391 r90 bottom value=10.0k
R105 "RK73Z1ETTP" 0402L 54.28,41.551 r90 top value=0
R106 "RMCF0402FT49R9" 0402L 55.129,41.554 r90 top value=49.9
R107 "CRCW0402100KJNED" 0402L 54.788,37.352 r0 bottom value=100k
R108 "CRCW040254K9FKED" 0402L 56.409,31.434 r180 bottom value=54.9k
R109 "CRCW040227K4FKED" 0402L 54.774,39.573 r180 top value=27.4k
R110 "CRCW040254K9FKED" 0402L 58.307,31.445 r180 bottom value=54.9k
R111 "CRCW0402200KJNED" 0402L 58.965,31.369 r180 top value=200k
R112 "CRCW04023K65FKED" 0402L 59.03,35.992 r270 top value=3.65k
R113 "RMCF0402JT10R0" 0402L 55.891,32.69 r270 bottom value=10.0
R114 "CRCW0402150KJNED" 0402L 59.092,35.458 r180 bottom value=150k
R115 "CRCW04029K76FKED" 0402L 59.092,34.646 r180 bottom value=9.76k
R116 "CRCW04026K04FKED" 0402L 60.87,32.182 r180 top value=6.04k
R117 "CRCW04026K98FKED" 0402L 60.884,31.471 r180 top value=6.98k
R118 "ESR03EZPJ102" 0603L 59.32,33.269 r0 top value=1.0k
R119 "CRCW0603100KFKEA" 0603L 56.629,34.522 r270 bottom value=100k
R120 "CRCW06039K09FKEA" 0603L 59.356,34.438 r180 top value=9.09k
R121 "RK73H1ETTP1002F" 0402L 59.106,33.045 r180 bottom value=10.0k
R201 "KRL3216E-C-R001-J-T5" FP-KRL3216E-C-R001-J-T5_0612-MFG 70.386,54.523 r90 top value=1m (schematic designator R01)
R202 "CRCW04029K76FKED" 0402L 76.457,41.987 r0 bottom value=9.76k (schematic designator R02)
R203 "RK73Z1ETTP" 0402L 80.874,39.52 r180 top value=0 (schematic designator R03)
R204 "RK73H1ETTP1002F" 0402L 78.644,41.095 r90 bottom value=10.0k (schematic designator R04)
R205 "RK73Z1ETTP" 0402L 78.461,41.476 r90 top value=0 (schematic designator R05)
R206 "CRCW0402249RFKED" 0402L 79.251,41.453 r90 top value=249 (schematic designator R06)
R207 "CRCW040254K9FKED" 0402L 82.858,33.554 r0 top value=54.9k (schematic designator R07)
R208 "CRCW0402100KJNED" 0402L 82.869,31.717 r180 top value=100k (schematic designator R08)
R209 "CRCW040227K4FKED" 0402L 78.949,39.444 r180 top value=27.4k (schematic designator R09)
R210 "CRCW040254K9FKED" 0402L 82.855,32.637 r180 top value=54.9k (schematic designator R10)
R301 "KRL3216E-C-R001-J-T5" FP-KRL3216E-C-R001-J-T5_0612-MFG 92.611,54.53 r90 top value=1m (schematic designator R01)
R302 "CRCW04029K76FKED" 0402L 99.012,41.994 r0 bottom value=9.76k (schematic designator R02)
R303 "RK73Z1ETTP" 0402L 103.429,39.527 r180 top value=0 (schematic designator R03)
R304 "RK73H1ETTP1002F" 0402L 101.199,41.102 r90 bottom value=10.0k (schematic designator R04)
R305 "RK73Z1ETTP" 0402L 101.016,41.483 r90 top value=0 (schematic designator R05)
R306 "CRCW0402249RFKED" 0402L 101.806,41.46 r90 top value=249 (schematic designator R06)
R307 "CRCW040254K9FKED" 0402L 105.083,33.561 r0 top value=54.9k (schematic designator R07)
R308 "CRCW0402100KJNED" 0402L 105.094,31.724 r180 top value=100k (schematic designator R08)
R309 "CRCW040227K4FKED" 0402L 101.504,39.451 r180 top value=27.4k (schematic designator R09)
R310 "CRCW040254K9FKED" 0402L 105.08,32.614 r180 top value=54.9k (schematic designator R10)
R401 "KRL3216E-C-R001-J-T5" FP-KRL3216E-C-R001-J-T5_0612-MFG 23.825,54.627 r90 top value=1m (schematic designator R01)
R402 "CRCW04029K76FKED" 0402L 30.175,42.091 r0 bottom value=9.76k (schematic designator R02)
R403 "RK73Z1ETTP" 0402L 34.592,39.624 r180 top value=0 (schematic designator R03)
R404 "RK73H1ETTP1002F" 0402L 32.362,41.199 r90 bottom value=10.0k (schematic designator R04)
R405 "RK73Z1ETTP" 0402L 32.179,41.58 r90 top value=0 (schematic designator R05)
R406 "CRCW0402249RFKED" 0402L 32.969,41.557 r90 top value=249 (schematic designator R06)
R407 "CRCW040254K9FKED" 0402L 36.297,33.658 r0 top value=54.9k (schematic designator R07)
R408 "CRCW0402100KJNED" 0402L 36.308,31.821 r180 top value=100k (schematic designator R08)
R409 "CRCW040227K4FKED" 0402L 32.667,39.548 r180 top value=27.4k (schematic designator R09)
R410 "CRCW040254K9FKED" 0402L 36.294,32.741 r180 top value=54.9k (schematic designator R10)
R500 "CRCW06031R00FKEA" 0603L 50.165,14.199 r90 top value=1.00
R501 "CRCW06031R00FKEA" 0603L 75.311,70.637 r90 top value=1.00
R502 "RCL12251R00FKEG" FP-RCL12251R00FKEG_2512-MFG 64.999,20.041 r90 top value=1
R503 "CRCW06031R00FKEA" 0603L 12.802,13.411 r90 top value=1.00
R504 "CRCW06031R00FKEA" 0603L 39.014,70.155 r90 top value=1.00
R505 "RK73Z1ETTP" 0402L 82.855,35.281 r0 top value=0
R506 "RK73Z1ETTP" 0402L 105.004,35.255 r0 top value=0
R507 "RK73Z1ETTP" 0402L 36.271,35.331 r0 top value=0
R600 "CRCW06031R00JNEA" 0603L 110.619,65.425 r90 bottom value=1.0
R601 "CRCW06031R00JNEA" 0603L 102.186,66.026 r90 top value=1.0
R602 "CRCW060310K0FKEA" 0603L 110.592,62.428 r90 bottom value=10.0k
R603 "CRCW060349R9FKEA" 0603L 92.707,72.185 r0 bottom value=49.9
R604 "CRCW060349R9FKEA" 0603L 84.328,71.255 r270 bottom value=49.9
R605 "WK73S3ATTER200F" FP-WK73S3ATTER200F_1225-MFG 98.397,70.348 r270 bottom value=0.2
R606 "WK73S3ATTER200F" FP-WK73S3ATTER200F_1225-MFG 105.978,70.354 r270 bottom value=0.2
R607 "CRCW06031R00FKEA" 0603L 92.733,69.38 r0 bottom value=1.00
SH-J700 "M7582-05" Harwin_M7582-05 112.801,15.291 r90 top
SH-J701 "M7582-05" Harwin_M7582-05 110.211,15.24 r90 top
SH-J702 "M7582-05" Harwin_M7582-05 107.518,15.24 r90 top
SH-J703 "M7582-05" Harwin_M7582-05 88.392,13.894 r0 top
T500 "CB70-14-CY" CB70-14-CY 39.98,12.116 r90 top
T501 "CB70-14-CY" CB70-14-CY 65.938,66.624 r270 top
T502 "CB70-14-CY" CB70-14-CY 22.86,12.243 r90 top
T503 "CB70-14-CY" CB70-14-CY 49.632,66.599 r270 top
TP500 "VIN+" Keystone_5019 50.089,10.439 r270 top
TP501 "VOUT+" Keystone_5019 75.336,75.311 r270 top
TP502 "VIN-" Keystone_5019 12.954,9.296 r270 top
TP503 "VOUT-" Keystone_5019 38.989,75.387 r270 top
U101 "LMG708B5VBTRQ1" VBT0022B-MFG 53.125,34.12 r270 top
U201 "LMG708B5VBTRQ1" VBT0022B-MFG 77.508,34.028 r270 top (schematic designator U01)
U301 "LMG708B5VBTRQ1" VBT0022B-MFG 99.733,34.035 r270 top (schematic designator U01)
U401 "LMG708B5VBTRQ1" VBT0022B-MFG 30.947,34.132 r270 top (schematic designator U01)
ZZ700 "This Assembly Note is for PCB labels only" AssemblyNoteLabel 15.545,118.11 r0 top
ZZ701 "These assemblies are ESD sensitive, ESD precautions shall be observed." AssemblyNote 15.824,122.123 r0 top
ZZ702 "These assemblies must be clean and free from flux and all contaminants. Use of no clean flux is not acceptable." AssemblyNote 15.951,125.705 r0 top
ZZ703 "These assemblies must comply with workmanship standards IPC-A-610 Class 2, unless otherwise specified." AssemblyNote 16.002,129.337 r0 top

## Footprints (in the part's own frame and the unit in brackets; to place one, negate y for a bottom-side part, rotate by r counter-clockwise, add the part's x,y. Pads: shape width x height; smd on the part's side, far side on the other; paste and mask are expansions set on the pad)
0402L [mm] "0402 from SM-752 data"
  rect 0.6x0.5 smd: 1(-0.5,0) 2(0.5,0)
  body extent -0.55,-0.3 0.55,0.3, height 0.6
0603L [mm] "0603 from SM-752 data"
  rect 0.8x0.85 smd: 1(-0.7,0) 2(0.7,0)
  body extent -0.87,-0.47 0.87,0.47, height 1
0805 [mm] "0805 from SM-752 data"
  rect 1.3x1.5 smd: 1(-0.85,0) 2(0.85,0)
  silkscreen extent -1.72,-0.97 1.72,0.97, body extent -1.1,-0.72 1.1,0.72, height 1.45
0805L [mm] "0805 from SM-752 data"
  rect 1.1x1.4 smd: 1(-0.75,0) 2(0.75,0)
  body extent -1.1,-0.72 1.1,0.72, height 1.45
1210_220 [mm] "1210"
  rect 1.3x2.7 smd: 1(-1.45,0) 2(1.45,0)
  silkscreen extent -2.32,-1.57 2.32,1.57, body extent -1.7,-1.35 1.7,1.35, height 2.2
AssemblyNote [mm] "Assembly Note"
AssemblyNoteLabel [mm] "Assembly Note for PCB Labels"
CB70-14-CY [mil] "Terminal 90A Lug"
  rect 680x500 hole 254 copper offset -90,0 paste-99999: 1(0,0)
  body extent -1300,-260 250,260, height 714
CE_Mark_5mm [mm] "Minimum text height for CE Mark"
  silkscreen extent -20.46,-38.69 -13.47,-33.7
CONN_5-146261-1 [mm] "Sullins"
  rect 1.5x1.5 hole 1.02: 1(-1.27,0)
  round 1.5 hole 1.02: 2(1.27,0)
  silkscreen extent -3.68,-1.27 2.54,1.27, body extent -2.51,-1.27 2.51,1.27, height 10.87
DNK0008A [mm] "SON, 8-Leads, Body 5x6mm"
  rrect39% 0.86x0.51 smd paste-0.05 mask-0.05: 1(-2.82,1.905) 2(-2.82,0.635) 3(-2.82,-0.635) 4(-2.82,-1.905) 5(2.82,-1.905) 6(2.82,-0.635) 7(2.82,0.635) 8(2.82,1.905)
  rrect40% 0.25x0.555 on Bottom Solder: 9(-0.83,-2.372) 9(-0.83,2.372)
  rrect40% 0.25x0.555 on Bottom Paste: 9(-0.83,-2.372) 9(-0.83,2.372)
  rrect11% 0.95x1.13 on Bottom Paste: 9(-0.535,-1.33) 9(-0.535,0) 9(-0.535,1.33) 9(0.615,-1.33) 9(0.615,0) 9(0.615,1.33) 9(1.765,-1.33) 9(1.765,0) 9(1.765,1.33)
  rrect3% 3.58x4 on Bottom Solder: 9(0.75,0)
  rrect5% 4.34x5.4 smd paste-3 mask-3: 9(1.08,0)
  body extent -3.05,-2.55 3.05,2.55, height 1.06
FCC_disclaimer [mm]
FP-GCJ32DC72A475KE01L_1210-MFG [mm]
  rrect9% 1.1x2.05 smd paste+0 mask+0: 1(-1.65,0) 2(1.65,0)
  silkscreen extent -1.8,-1.4 1.8,1.4, body extent -1.6,-1.25 1.6,1.25, height 2.3
FP-GCM32EC71E226KE36L_1210-MFG [mm]
  rrect9% 1.1x2.05 smd paste+0 mask+0: 1(-1.65,0) 2(1.65,0)
  silkscreen extent -1.78,-1.43 1.78,1.43, body extent -2.3,-1.53 2.3,1.53, height 0.25
FP-KRL3216E-C-R001-J-T5_0612-MFG [mm] "Recommended Land Pattern"
  rrect10% 1x3.4 smd paste+0 mask+0: 1(-0.7,0) 2(0.7,0)
  silkscreen extent -0.9,-2.07 0.9,2.07, body extent -1.3,-1.8 1.3,1.8, height 0.25
FP-RCL12251R00FKEG_2512-MFG [mm]
  rrect6% 1.6x6.6 smd paste+0 mask+0: 1(-1.4,0) 2(1.4,0)
  silkscreen extent -0.23,-3.25 0.23,3.25, body extent -1.6,-3.15 1.6,3.15, height 0.8
FP-TCQE157M016R0025E_2917-MFG [mm] "Recommended Land Pattern"
  rrect5% 2x3 smd paste+0 mask+0: 1(-3,0) 2(3,0)
  silkscreen extent -3.75,-2.25 4.87,2.25, body extent -3.65,-2.15 3.65,2.15, height 4.3
FP-TSW-103-07-G-T_HDR9-MFG [mm]
  rrect6% 1.57x1.57 hole 1.02 paste-2539.97 mask+0: 1(-2.54,-2.54)
  round 1.57 hole 1.02 paste-2539.97 mask+0: 2(-2.54,0) 3(-2.54,2.54) 4(0,-2.54) 5(0,0) 6(0,2.54) 7(2.54,-2.54) 8(2.54,0) 9(2.54,2.54)
  silkscreen extent -4.66,-3.88 3.94,3.88, body extent -4.04,-3.98 4.04,3.98, height 0.25
FP-VCHA105D-4R7MS6_SMT_10MM85_10MM0-MFG [mm]
  rrect3% 3.99x5 smd paste+0 mask+0: 1(-4.445,0) 2(4.445,0)
  body extent -6.54,-5.25 6.54,5.25, height 0.25
FP-VCUD128T-4R7MS8_SMT_IND_13MM3_12MM8-MFG [mm] "Recommended Land Pattern"
  rrect3% 4x13.2 smd paste+0 mask+0: 1(-5.35,0) 2(5.35,0)
  silkscreen extent -8.02,-6.55 2.98,6.55, body extent -7.45,-6.7 7.45,6.7, height 0.25
FP-WK73S3ATTER200F_1225-MFG [mm] "Recommended Land Pattern"
  rrect9% 1.15x6.4 smd paste+0 mask+0: 1(-1.375,0) 2(1.375,0)
  silkscreen extent -0.43,-3.22 0.43,3.22, body extent -1.55,-3.15 1.55,3.15, height 0.7
Harwin_M7582-05 [mm] "Single Operation 2.54mm Pitch Open Top Jumper Socket"
  body extent -2.5,-1.2 2.5,1.2, height 6
IEC_HotSurface_Small [mm]
  silkscreen extent -2.72,-2.36 2.72,2.35
Keystone_1902E [mil] "Hex Standoff, 4-40 threaded, nylon"
  round 1 on Mech3: 0(0,0)
  body extent -145,-126 146,126, height 1001
Keystone_5019 [mm] "Test Point, Miniature, SMT"
  rect 3.8x2.03 smd: 1(0,0)
  silkscreen extent -2.31,-1.42 2.31,1.42, body extent -1.9,-1.02 1.9,1.02, height 2.29
Net-Tie_10mil [mil] "10mil net tie, no solder mask opening, no solder paste"
  rect 10x10 smd paste-5 mask-5: 1(-10,0) 2(10,0)
  Layer 1 region: -6,5 6,5 6,-5 -6,-5
"NY PMS 440 0025 PH"#1 [mm] "4-40 nylon screw and mounting hole"
  round 8 hole 3.2: 1(-0.07,-0.125)
  body extent -3.3,-3.3 3.3,3.3, height 2.69
"NY PMS 440 0025 PH"#2 [mm] "4-40 nylon screw and mounting hole"
  round 8 hole 3.2: 1(0,0)
  body extent -3.3,-3.3 3.3,3.3, height 2.69
Samtec_HTSW-103-07-G-S [mm] "Samtec 100mil, 1x3, 230 mil above insulator"
  rrect6% 1.65x1.65 hole 1.016: 1(-2.54,0)
  round 1.65 hole 1.016: 2(0,0) 3(2.54,0)
  silkscreen extent -4.57,-1.27 3.81,1.27, body extent -3.81,-1.27 3.81,1.27, height 8.38
Samtec_MMCX-J-P-H-ST-TH1 [mm] "Connector, MMCX, TH"
  round 1.2 hole 0.84: 1(0,0) 2(-1.27,1.27) 3(1.27,1.27) 4(1.27,-1.27) 5(-1.27,-1.27)
  silkscreen extent -1.75,-1.75 1.75,1.75, body extent -1.75,-1.75 1.75,1.75, height 4.35
SM_RADIAL_H13 [mm] "12.5 x 13.5mm:  Panasonic H13"
  rect 5.7x2 smd: 1(-4.85,0) 2(4.85,0)
  silkscreen extent -6.85,-6.85 6.85,6.85, body extent -6.85,-6.85 6.85,6.85, height 14
TI_Stacked_Overlay_Small [mm]
  silkscreen extent -27.59,-38.69 -6.34,-33.7
TSW-105-07-X-S [mm] "Samtec 100mil, 1x5, 230 mil above insulator"
  rrect6% 1.65x1.65 hole 1.016: 1(-5.08,-0.025)
  round 1.65 hole 1.016: 2(-2.54,0) 3(0,0) 4(2.54,0) 5(5.08,0)
  silkscreen extent -7.05,-1.25 6.37,1.25, body extent -6.35,-1.27 6.35,1.27, height 8.38
VBT0022B-MFG [mm] "Recommended Land Pattern"
  round 0.234 smd paste+0 mask+0: 1(-1.837,2.762)
  rrect40% 0.7x0.25 smd paste+0 mask+0: 2(-2.1,2.125) 3(-2.1,1.625) 4(-2.1,1.125) 5(-2.1,0.625) 6(-2.1,0.125) 10(2.1,0.125) 11(2.1,0.625) 12(2.1,1.125) 13(2.1,1.625) 14(2.1,2.125)
  rrect25% 0.8x2.35 smd paste-1000 mask-1000: 7(-2.1,-1.675) 9(2.1,-1.675)
  rrect10% 2x3.15 smd paste-1000 mask-1000: 8(0,-1.675)
  round 0.265 smd paste+0 mask+0: 15(1.875,2.675)
  rrect40% 0.25x0.7 smd paste+0 mask+0: 16(1.25,2.85) 17(0.75,2.85) 18(0.25,2.85) 19(-0.25,2.85) 20(-0.75,2.85) 21(-1.25,2.85)
  rrect10% 2.6x2.1 smd paste-1000 mask-1000: 22(0,1.15)
  Layer 1 region: -2.4,2.5 -2.419,2.504 -2.435,2.515 -2.446,2.531 -2.45,2.55 -2.45,2.55 -2.45,2.7 -2.443,2.725 -2.425,2.743 -2.4,2.75 -2.4,2.75 -2.05,2.75 -2.012,2.758 -1.979,2.779 -1.958,2.812 -1.95,2.85 -1.95,2.85 -1.95,3.15 -1.943,3.175 -1.925,3.193 -1.9,3.2 -1.9,3.2 -1.75,3.2 -1.725,3.193 -1.707,3.175 -1.7,3.15 -1.7,3.15 -1.7,2.55 -1.704,2.531 -1.715,2.515 -1.731,2.504 -1.75,2.5 -1.75,2.5
  Layer 1 region: 2.4,2.5 2.419,2.504 2.435,2.515 2.446,2.531 2.45,2.55 2.45,2.55 2.45,2.7 2.446,2.719 2.435,2.735 2.419,2.746 2.4,2.75 2.4,2.75 2.05,2.75 2.012,2.758 1.979,2.779 1.958,2.812 1.95,2.85 1.95,2.85 1.95,3.15 1.946,3.169 1.935,3.185 1.919,3.196 1.9,3.2 1.9,3.2 1.75,3.2 1.725,3.193 1.707,3.175 1.7,3.15 1.7,3.15 1.7,2.55 1.704,2.531 1.715,2.515 1.731,2.504 1.75,2.5 1.75,2.5
  silkscreen extent -3.17,-3.37 2.6,3.3, body extent -2.25,-3 2.25,3, height 0.85
VCHA105D [mm] "SMD, 2-Leads, Body 10.85x10mm"
  rrect2% 4.1x4.95 smd: 1(-4.75,0) 2(4.75,0)
  body extent -5.6,-5.15 5.6,5.15, height 5.4
WEEE_Minimum [mm] "WEEElie bin"
  silkscreen extent -19.39,-40.57 -14.44,-33.54

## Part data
C101 C102 C103 C201 C202 C203 C301 C302 C303 C401 C402 C403: library part CMP-0082268-1, "CAP, CERM, 4.7 µF, 100 V,+/- 10%, X7S, AEC-Q200 Grade 1, 1210", Cap_Case=1210, Manufacturer=MuRata, Supplier Part Number 1=490-14484-1-ND, TempCo=X7S, Tolerance_%=10%, Value1="0.001 ohm", Value2=100V, ValueDisplayed=4.7µF
C104 C204 C304 C404: library part CMP-0007980-2, "CAP, CERM, 1 uF, 100 V, +/- 10%, X7S, AEC-Q200 Grade 1, 0805", Cap_Case=0805, Manufacturer=TDK, Supplier Part Number 1=445-6974-1-ND, TempCo=X7S, Tolerance_%=10%, Value1="0.008255 ohm", Value2=100V, ValueDisplayed=1uF
C105 C205 C305 C405: library part CMP-0078500-1, "CAP, CERM, 0.1 µF,  VAC/100 VDC,+/- 20%, X7R, AEC-Q200 Grade 1, 0603", Cap_Case=0603, Manufacturer="Taiyo Yuden", Supplier Part Number 1=587-5544-1-ND, TempCo=X7R, Tolerance_%=20%, Value2=100V, ValueDisplayed=0.1µF
C106 C206 C306 C406: library part CMP-0006333-2, "CAP, CERM, 0.01 uF, 100 V, +/- 10%, X7S, AEC-Q200 Grade 1, 0402", Cap_Case=0402, Manufacturer=TDK, Supplier Part Number 1=445-6910-1-ND, TempCo=X7S, Tolerance_%=10%, Value1="0.410191 ohm", Value2=100V, ValueDisplayed=0.01uF
C107 C207 C307 C407: library part CMP-0006332-2, "CAP, CERM, 1000 pF, 100 V, +/- 10%, X7S, AEC-Q200 Grade 1, 0402", Cap_Case=0402, Manufacturer=TDK, Supplier Part Number 1=445-6904-1-ND, TempCo=X7S, Tolerance_%=10%, Value1="2.71151 ohm", Value2=100V, ValueDisplayed=1000pF
C109 C125 C126 C209 C309 C409: library part CMP-0080610-1, "CAP, CERM, 0.1 µF, 25 V,+/- 10%, X7R, AEC-Q200 Grade 1, 0402", Cap_Case=0402, Manufacturer=TDK, Supplier Part Number 1=445-6902-1-ND, TempCo=X7R, Tolerance_%=10%, Value2=25V, ValueDisplayed=0.1µF
C110 C210 C310 C410: library part CMP-0081052-1, "CAP, CERM, 4.7 µF, 16 V,+/- 10%, X5R, AEC-Q200 Grade 3, 0603", Cap_Case=0603, Manufacturer=MuRata, Supplier Part Number 1=490-12319-1-ND, TempCo=X5R, Tolerance_%=10%, Value2=16V, ValueDisplayed=4.7µF
C111 C112 C113 C114 C115 C116 C117 C211 C212 C213 C214 C215 C216 C217 C311 C312 C313 C314 C315 C316 C317 C411 C412 C413 C414 C415 C416 C417: library part CMP-0122305-1, "Ceramic Capacitor for Automotive 22uF ±10% 25VDC X7S 1210 Embossed T/R", Manufacturer=Murata, Operating Temperature Range="-55°C to +125°C", TempCo=22%, Temperature Characteristic=X7S, Tolerance_%=10%, ValueDisplayed=22uF
C118 C119 C120 C218 C219 C220 C318 C319 C320 C418 C419 C420: library part CMP-0124500-1, "Cap Tant Polymer 150uF 16VDC E CASE 20%( 7.3 X 4.3 X 4.1mm) J Lead SMD 7343-43 0.025 Ohm 125C T/R", Digikey Part Number=478-TCQE157M016R0025ECT-ND, Leakage Current=240uA, Manufacturer="KYOCERA AVX", Mouser Part Number=581-TCQE157M016R25E, Operating Temperature Range="-55°C to +125°C", Tolerance_%=20%, ValueDisplayed=150uF
C121 C221 C321 C421: library part CMP-0081259-1, "CAP, CERM, 1 µF, 35 V,+/- 10%, X7R, AEC-Q200 Grade 1, 0603", Cap_Case=0603, Manufacturer=TDK, Supplier Part Number 1=445-174339-1-ND, TempCo=X7R, Tolerance_%=10%, Value2=35V, ValueDisplayed=1µF
C122 C222 C322 C422: library part CMP-0860832-1, "CAP, CERM, 47 pF, 50 V,+/- 5%, C0G/NP0, AEC-Q200 Grade 1, 0402", Cap_Case=0402, Manufacturer=TDK, TempCo=C0G/NP0, Tolerance_%=5%, Value2=50V, ValueDisplayed=47pF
